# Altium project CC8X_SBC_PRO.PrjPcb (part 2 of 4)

## Sheet 06 - JTAG, SWD, MicroSD, Mini PCIe, MicroSIM.SchDoc: JTAG, SWD, MicroSD, Mini PCIe, MicroSIM
size A3; PageSetup: Record=PageOptions¦CenterHorizontal=True¦CenterVertical=True¦PrintScale=0.70¦XCorrection=1.00¦YCorrection=1.00¦PrintKind=0¦BorderSize=5000000¦LeftOffset=0¦BottomOffset=0¦Orientation=2¦PaperLength=4200¦PaperWidth=2970¦Scale=100¦PaperSource=7¦PrintQuality=600¦MediaType=1¦DitherType=10¦PaperKind=A4¦PrintScaleMode=1; Author: Juan Anzola; SheetNumber: 6; SheetTotal: 17
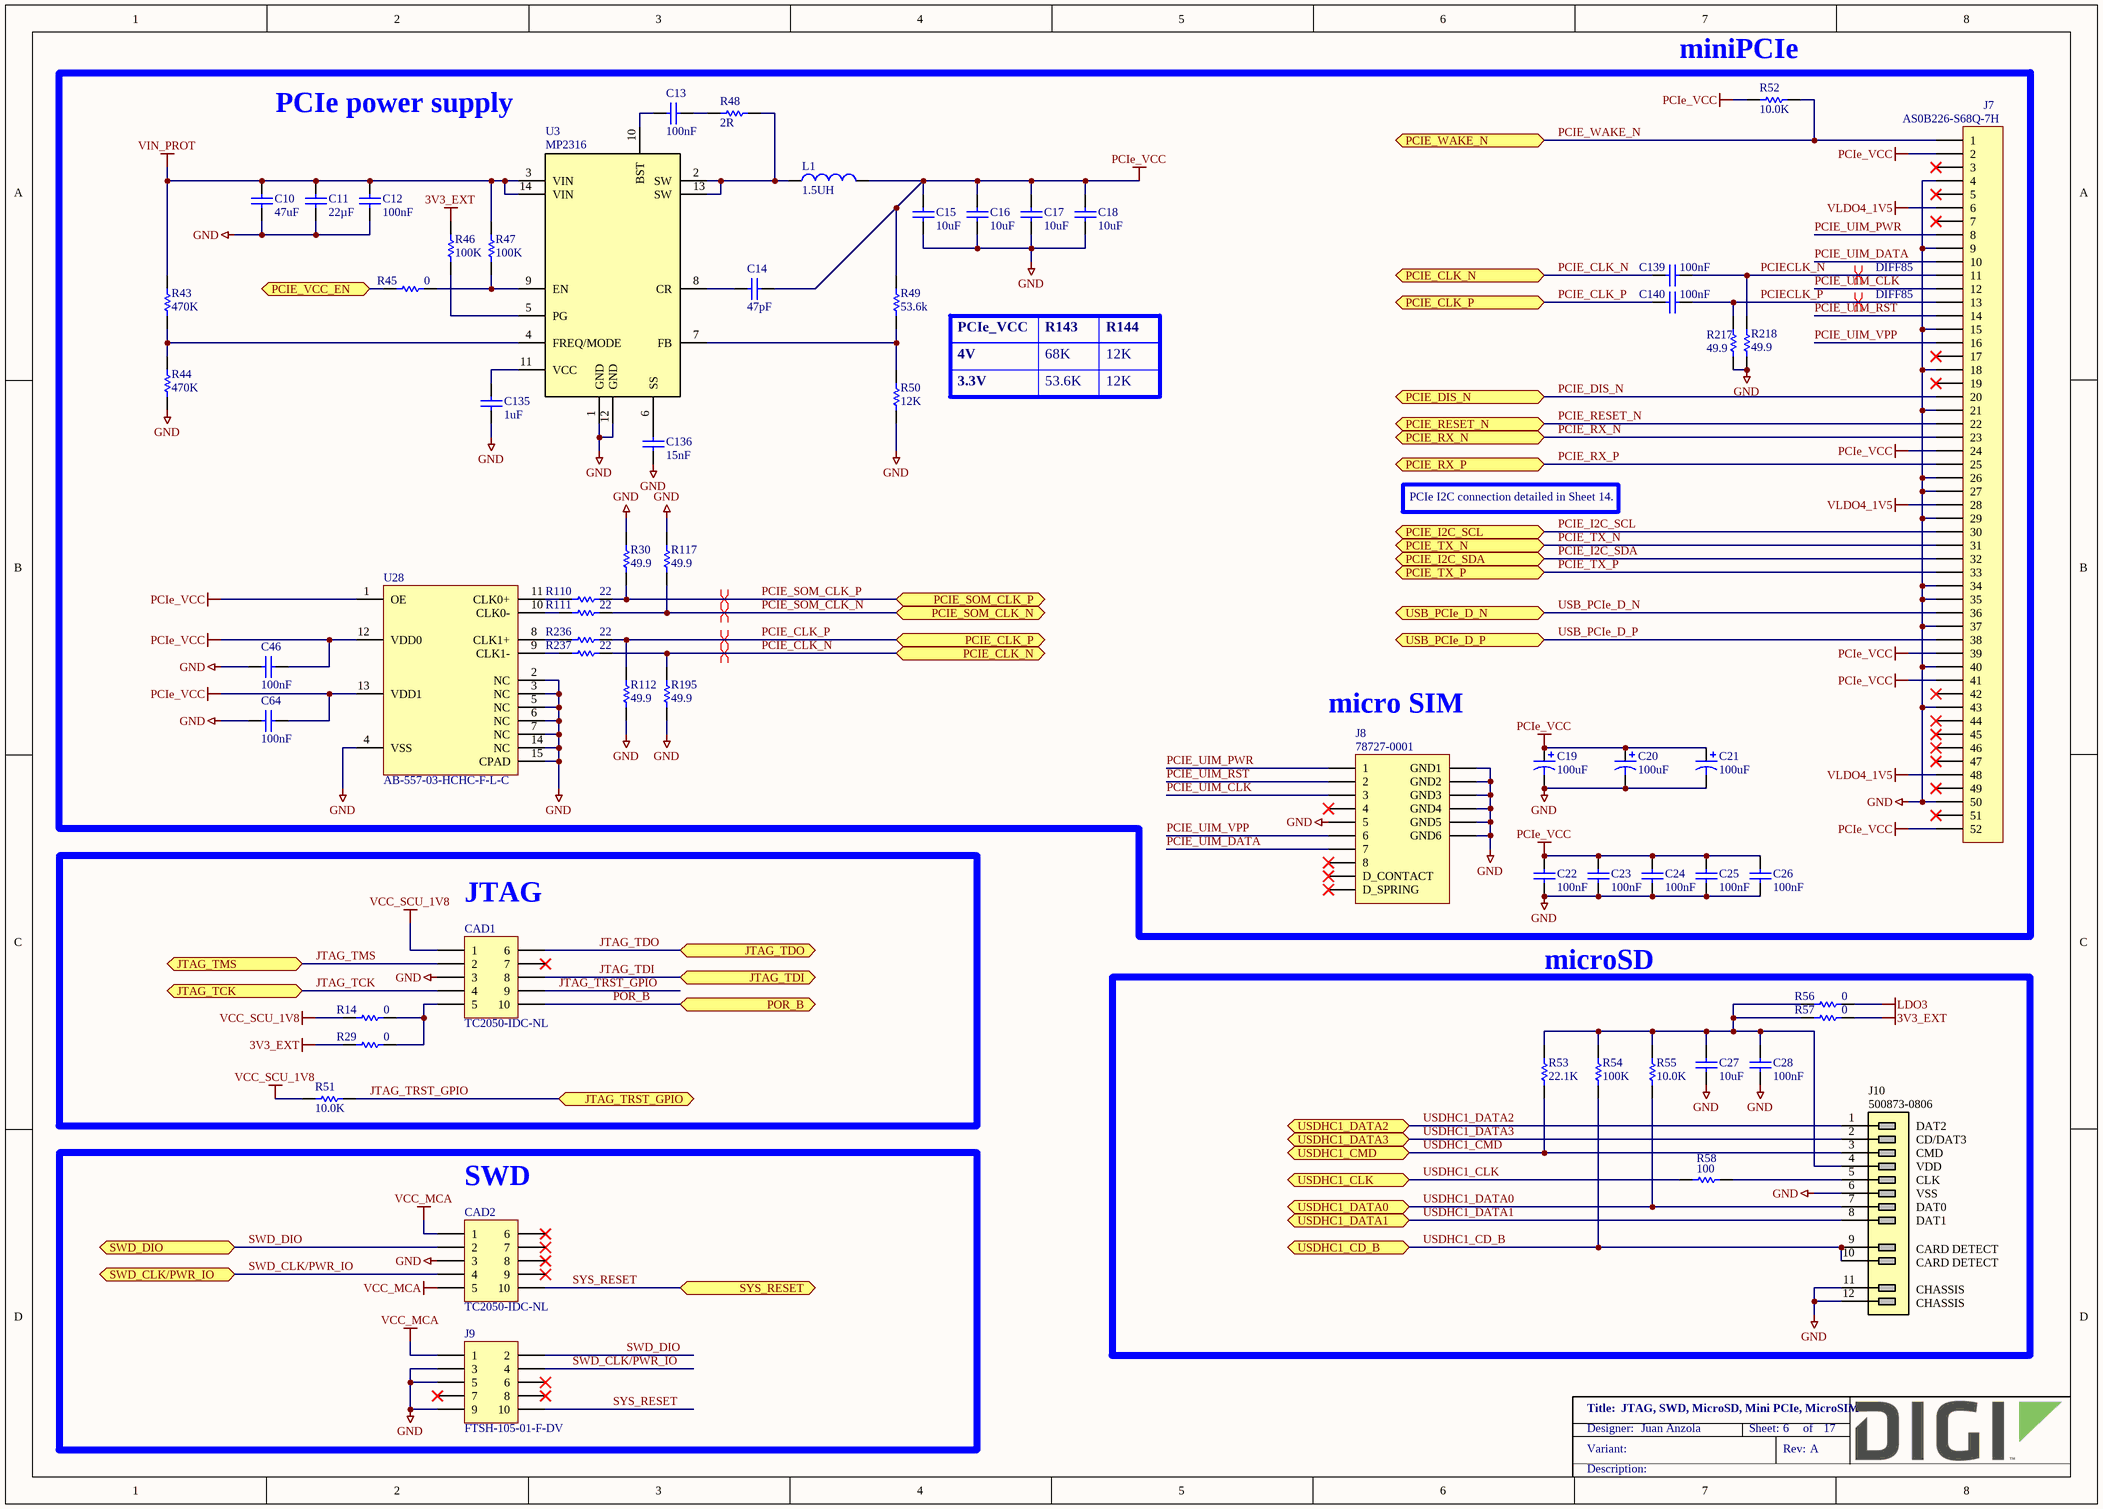
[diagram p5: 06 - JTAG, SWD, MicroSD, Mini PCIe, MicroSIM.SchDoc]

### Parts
C10  47uF  [CAPC2013X145N]
C11  22µF  [CAPC1608X90N]
C12  100nF  [CAPC1005X55N]
C13  100nF  [CAPC1005X55N]
C14  47pF  [CAPC1005X55N]
C15  10uF  [CAPC2013X135N]
C16  10uF  [CAPC2013X135N]
C17  10uF  [CAPC2013X135N]
C18  10uF  [CAPC2013X135N]
C19  100uF  [CAPMP3216X120N]
C20  100uF  [CAPMP3216X120N]
C21  100uF  [CAPMP3216X120N]
C22  100nF  [CAPC1005X55N]
C23  100nF  [CAPC1005X55N]
C24  100nF  [CAPC1005X55N]
C25  100nF  [CAPC1005X55N]
C26  100nF  [CAPC1005X55N]
C27  10uF  [CAPC1005X55N]
C28  100nF  [CAPC1005X55N]
C46  100nF  [CAPC1005X55N]
C64  100nF  [CAPC1005X55N]
C135  1uF  [CAPC1608X90N]
C136  15nF  [CAPC1005X55N]
C139  100nF  [CAPC1005X55N]
C140  100nF  [CAPC1005X55N]
CAD1  TC2050-IDC-NL  [TC_TC2050-IDC-NL]  (no BOM)
CAD2  TC2050-IDC-NL  [TC_TC2050-IDC-NL]  (no BOM)
J7  Manufacturer_Part_Number: AS0B226-S68Q-7H  [FOXCONN_AS0B221-S68Q-7H]  (hidden comment: PCIe Minicard)
J8  78727-0001  [MOLEX_78727-0001]
J9  FTSH-105-01-F-DV  [SAMTEC_FTSH-105-01-F-DV]
J10  500873-0806  [MOLEX_500873-0806]
L1  1.5UH  [INDM_SRP4020TA]
R14  0  [RESC1005X40N]
R29  0  [RESC1005X40N]
R30  49.9  [RESC1005X40N]
R43  470K  [RESC1005X40N]
R44  470K  [RESC1005X40N]
R45  0  [RESC1005X40N]
R46  100K  [RESC1005X40N]
R47  100K  [RESC1005X40N]
R48  2R  [RESC1609X55N]
R49  53.6k  [RESC1609X55N]
R50  12K  [RESC1609X55N]
R51  10.0K  [RESC1005X40N]
R52  10.0K  [RESC1005X40N]
R53  22.1K  [RESC1005X40N]
R54  100K  [RESC1005X40N]
R55  10.0K  [RESC1005X40N]
R56  0  [RESC1005X40N]
R57  0  [RESC1005X40N]
R58  100  [RESC1005X40N]
R110  22  [RESC1005X40N]
R111  22  [RESC1005X40N]
R112  49.9  [RESC1005X40N]
R117  49.9  [RESC1005X40N]
R195  49.9  [RESC1005X40N]
R217  49.9  [RESC1005X40N]
R218  49.9  [RESC1005X40N]
R236  22  [RESC1005X40N]
R237  22  [RESC1005X40N]
U3  MP2316  [QFN_MPS_MP2316]
U28  AB-557-03-HCHC-F-L-C  [QFN50P320X250X90-15T140X210N]

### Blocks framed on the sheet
JTAG: CAD1 R14 R29 R51
microSD: C27 C28 J10 R53-R58
SWD: CAD2 J9

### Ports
JTAG_TCK (bidir), JTAG_TDI (bidir), JTAG_TDO (bidir), JTAG_TMS (bidir), JTAG_TRST_GPIO (bidir), PCIE_CLK_N (bidir), PCIE_CLK_P (bidir), PCIE_DIS_N (bidir), PCIE_I2C_SCL (bidir), PCIE_I2C_SDA (bidir), PCIE_RESET_N (bidir), PCIE_RX_N (bidir), PCIE_RX_P (bidir), PCIE_SOM_CLK_N (bidir), PCIE_SOM_CLK_P (bidir), PCIE_TX_N (bidir), PCIE_TX_P (bidir), PCIE_VCC_EN (bidir), PCIE_WAKE_N (bidir), POR_B (bidir), SWD_CLK/PWR_IO (bidir), SWD_DIO (bidir), SYS_RESET (bidir), USB_PCIe_D_N (bidir), USB_PCIe_D_P (bidir), USDHC1_CD_B (bidir), USDHC1_CLK (bidir), USDHC1_CMD (bidir), USDHC1_DATA0 (bidir), USDHC1_DATA1 (bidir), USDHC1_DATA2 (bidir), USDHC1_DATA3 (bidir)

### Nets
3V3_EXT: R29.1 R46.1 R57.2
GND: C10.1 C11.1 C12.1 C15.1 C16.1 C17.1 C18.1 C19.2 C20.2 C21.2 C22.1 C23.1 C24.1 C25.1 C26.1 C27.1 C28.1 C46.2 C64.2 C135.1 C136.1 CAD1.3 CAD2.3 J7.4 J7.9 J7.15 J7.18 J7.21 J7.26 J7.27 J7.29 J7.34 J7.35 J7.37 J7.40 J7.43 J7.50 J8.5 J8.11(GND1) J8.12(GND2) J8.13(GND3) J8.14(GND4) J8.15(GND5) J8.16(GND6) J9.3 J9.5 J9.9 J10.6 J10.11 J10.12 R30.2 R44.1 R50.1 R112.1 R117.2 R195.1 R217.1 R218.1 U3.1(GND) U3.12(GND) U28.2(NC) U28.3(NC) U28.4(VSS) U28.5(NC) U28.6(NC) U28.7(NC) U28.14(NC) U28.15(CPAD)
LDO3: R56.2
PCIe_VCC: C14.2 C15.2 C16.2 C17.2 C18.2 C19.1 C20.1 C21.1 C22.2 C23.2 C24.2 C25.2 C26.2 C46.1 C64.1 J7.2 J7.24 J7.39 J7.41 J7.52 L1.2 R49.2 R52.2 U28.1(OE) U28.12(VDD0) U28.13(VDD1)
VCC_MCA: CAD2.1 CAD2.5 J9.1
VCC_SCU_1V8: CAD1.1 R14.1 R51.2
VIN_PROT: C10.2 C11.2 C12.2 R43.2 R47.2 U3.3(VIN) U3.14(VIN)
VLDO4_1V5: J7.6 J7.28 J7.48
JTAG_TCK: CAD1.4 ; port JTAG_TCK
JTAG_TDI: CAD1.8 ; port JTAG_TDI
JTAG_TDO: CAD1.6 ; port JTAG_TDO
JTAG_TMS: CAD1.2 ; port JTAG_TMS
JTAG_TRST_GPIO: CAD1.9 R51.1 ; port JTAG_TRST_GPIO
PCIE_CLK_N: C139.1 R195.2 R237.2 ; port PCIE_CLK_N
PCIE_CLK_P: C140.1 R112.2 R236.2 ; port PCIE_CLK_P
PCIE_DIS_N: J7.20 ; port PCIE_DIS_N
PCIE_I2C_SCL: J7.30 ; port PCIE_I2C_SCL
PCIE_I2C_SDA: J7.32 ; port PCIE_I2C_SDA
PCIE_RESET_N: J7.22 ; port PCIE_RESET_N
PCIE_RX_N: J7.23 ; port PCIE_RX_N
PCIE_RX_P: J7.25 ; port PCIE_RX_P
PCIE_SOM_CLK_N: R111.2 R117.1 ; port PCIE_SOM_CLK_N
PCIE_SOM_CLK_P: R30.1 R110.2 ; port PCIE_SOM_CLK_P
PCIE_TX_N: J7.31 ; port PCIE_TX_N
PCIE_TX_P: J7.33 ; port PCIE_TX_P
PCIE_UIM_CLK: J7.12 J8.3
PCIE_UIM_DATA: J7.10 J8.7
PCIE_UIM_PWR: J7.8 J8.1
PCIE_UIM_RST: J7.14 J8.2
PCIE_UIM_VPP: J7.16 J8.6
PCIE_VCC_EN: R45.1 ; port PCIE_VCC_EN
PCIE_WAKE_N: J7.1 R52.1 ; port PCIE_WAKE_N
PCIECLK_N: C139.2 J7.11 R218.2
PCIECLK_P: C140.2 J7.13 R217.2
POR_B: CAD1.10 ; port POR_B
SWD_CLK/PWR_IO: CAD2.4 J9.4 ; port SWD_CLK/PWR_IO
SWD_DIO: CAD2.2 J9.2 ; port SWD_DIO
SYS_RESET: CAD2.10 J9.10 ; port SYS_RESET
USB_PCIe_D_N: J7.36 ; port USB_PCIe_D_N
USB_PCIe_D_P: J7.38 ; port USB_PCIe_D_P
USDHC1_CD_B: J10.9 J10.10 R54.2 ; port USDHC1_CD_B
USDHC1_CLK: R58.1 ; port USDHC1_CLK
USDHC1_CMD: J10.3 R53.1 ; port USDHC1_CMD
USDHC1_DATA0: J10.7 R55.1 ; port USDHC1_DATA0
USDHC1_DATA1: J10.8 ; port USDHC1_DATA1
USDHC1_DATA2: J10.1 ; port USDHC1_DATA2
USDHC1_DATA3: J10.2 ; port USDHC1_DATA3
NetC13_1: C13.1 U3.10(BST)
NetC13_2: C13.2 R48.1
NetC14_1: C14.1 U3.8(CR)
NetC27_2: C27.2 C28.2 J10.4 R53.2 R54.1 R55.2 R56.1 R57.1
NetC135_2: C135.2 U3.11(VCC)
NetC136_2: C136.2 U3.6(SS)
NetCAD1_5: CAD1.5 R14.2 R29.2
NetJ10_5: J10.5 R58.2
NetL1_1: L1.1 R48.2 U3.2(SW) U3.13(SW)
NetR43_1: R43.1 R44.2 U3.4(FREQ/MODE)
NetR45_2: R45.2 R47.1 U3.9(EN)
NetR46_2: R46.2 U3.5(PG)
NetR49_1: R49.1 R50.2 U3.7(FB)
NetR110_1: R110.1 U28.11(CLK0+)
NetR111_1: R111.1 U28.10(CLK0-)
NetR236_1: R236.1 U28.8(CLK1+)
NetR237_1: R237.1 U28.9(CLK1-)

Not connected (* = marked no-connect by the designer): CAD1 7*; CAD2 6* 7* 8* 9*; J7 3* 5* 7* 17* 19* 42* 44* 45* 46* 47* 49* 51*; J8 4* 8* 9(D_CONTACT)* 10(D_SPRING)*; J9 6* 7* 8*

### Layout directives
differential pair; net class DIFF85: PCIECLK_N, PCIECLK_P
differential pair: PCIE_CLK_N, PCIE_CLK_P, PCIE_SOM_CLK_N, PCIE_SOM_CLK_P

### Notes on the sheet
- (near R52) miniPCIe
- (near U3) PCIe power supply
- PCIe_VCC
- 4V
- R143
- 68K
- R144
- 12K
- 3.3V
- 53.6K
- PCIe I2C connection detailed in Sheet 14.
- (near J8) micro SIM

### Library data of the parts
C10 = 1000501: CAP CER 47UF 6.3V 20% X5R 0805; Part_Type: Capacitor; Manufacturer: Taiyo Yuden; Manufacturer_Part_Number: JMK212BJ476MG-T; Digi_PN: 14050627; Component_Life_Cycle_State: Reviewed; Area: 6.4; Project: SDR Prototype RF Board
C11 = 1000998: CAP CER 22UF 10V 20% X5R 0603; Part_Type: Capacitor; Manufacturer: Samsung; Manufacturer_Part_Number: CL10A226MP8NUNE; Manufacturer_Alt_1: TDK Corporation; Manufacturer_Alt_1_Part_Number: C1608X5R1A226M080AC; Digi_PN: 14050684; Component_Life_Cycle_State: Reviewed; Area: 2.27; Project: ConnectCore i.MX6 module; Tolerance: 20
C12 C46 C64 = 1000918: CAP CER 0.1UF 50V 10% X7R 0402; Part_Type: Capacitor; Manufacturer: TDK Corporation; Manufacturer_Part_Number: C1005X7R1H104K050BB; Digi_PN: 14050715; Component_Life_Cycle_State: Reviewed; Area: 0.95; Project: DTM3.0
C13 = 1000006: CAP 100nF 16V 10% X7R 0402; Part_Type: Capacitor; Manufacturer: Murata; Manufacturer_Part_Number: GRM155R71C104KA88D; Digi_PN: 14050552; Component_Life_Cycle_State: CAD Reviewed; Area: 0.95; Project: KITT; Tolerance: 10
C14 = 1000007: CAP 47pF 50V 5% NP0 0402; Part_Type: Capacitor; Manufacturer: Murata; Manufacturer_Part_Number: GRM1555C1H470JA01D; Manufacturer_Alt_1: AVX Corporation; Manufacturer_Alt_1_Part_Number: 04025A470JAT2A; Note: 14050747 is Digi No. for GE WDNU; Digi_PN: 14050309; Component_Life_Cycle_State: CAD Reviewed; Area: 0.95; Project: KITT; Temp_Coef: C0G, NP0
C15-C18 = 1000111: CAP CER 10UF 16V 10% X5R 0805; Part_Type: Capacitor; Manufacturer: Murata; Manufacturer_Part_Number: GRM21BR61C106KE15L; Digi_PN: 14050701; Component_Life_Cycle_State: Proven; Area: 3.99; Project: Adjustable Foundation; Tolerance: 10
C19-C21 = 1001196: CAP TANT 100UF 6.3V 20% 1206; Part_Type: Capacitor; Manufacturer: Rohm; Manufacturer_Part_Number: TCTAL0J107M8R; Digi_PN: 14050490; Component_Life_Cycle_State: Reviewed; Area: 8.01; Project: CCWMX6_SBC board
C22-C26 C28 = 1000006: CAP 100nF 16V 10% X7R 0402; Part_Type: Capacitor; Manufacturer: Murata; Manufacturer_Part_Number: GRM155R71C104KA88D; Component_Life_Cycle_State: CAD Reviewed; Area: 0.95; Project: KITT; Tolerance: 10; Digi_PN: 14050552
C27 = 1001168: CAP CER 10UF 10V 20% X5R 0402; Part_Type: Capacitor; Manufacturer: Samsung; Manufacturer_Part_Number: CL05A106MP5NUNC; Digi_PN: 14050689; Component_Life_Cycle_State: Reviewed; Area: 0.95; Project: CCWMX6_SBC board
C135 = 1000110: CAP CER 1UF 25V 10% X5R 0603; Part_Type: Capacitor; Manufacturer: Murata; Manufacturer_Part_Number: GRM188R61E105KA12D; Manufacturer_Alt_1: AVX Corporation; Manufacturer_Alt_1_Part_Number: TMK107BJ105KA-T; Note: 14050758  = Digi No. for GE WDNU; Digi_PN: 14050618; Component_Life_Cycle_State: Reviewed; Area: 2.27; Project: Adjustable Foundation
C136 = 1000512: CAP CER 0.015UF 16V 10% X7R 0402; Part_Type: Capacitor; Manufacturer: Murata; Manufacturer_Part_Number: GRM155R71C153KA01D; Digi_PN: 14050713; Component_Life_Cycle_State: CAD Reviewed; Area: 0.95; Project: Cellular Proof of Concept
C139 C140 = 1000006: CAP 100nF 16V 10% X7R 0402; Part_Type: Capacitor; Manufacturer: Murata; Manufacturer_Part_Number: GRM155R71C104KA88D; Digi_PN: 14050552; Component_Life_Cycle_State: CAD Reviewed; Area: 0,95; Project: KITT; Tolerance: 10
CAD1 CAD2 = CAD0066: CBL PLUG-OF-NAILS 10-PIN; Part_Type: Test Point; Component_Life_Cycle_State: Created; Area: 8; Project: CCWMX6_SBC board
J7 = 1001130: SMCONN,MINI PCI EXP, 6.8MM HT; Part_Type: Connector; Manufacturer: Foxconn; Digi_PN: 18000349; Component_Life_Cycle_State: Reviewed; Area: 150; Project: CCWMX6_SBC board
J8 = 1001120: MEMORY CARD 6POS PUSH/PULL SMD; Part_Type: Connector; Manufacturer: Molex; Digi_PN: 18000638; Component_Life_Cycle_State: Reviewed; Area: 217; Project: CCWMX6_SBC board
J9 = 1000034: CONN HEADER 10POS DUAL .05" SMD; Part_Type: Connector; Manufacturer: Samtec; Note: 18000715 = Digi No. for GE WDNU; Digi_PN: 18000539; Component_Life_Cycle_State: Proven; Area: 43,55; Project: Adjustable Foundation
J10 = 1001118: CONN TRANSFLSH R/A PUSH-PUSH SMD; Part_Type: Connector; Manufacturer: Molex; Digi_PN: MB03015; Component_Life_Cycle_State: Reviewed; Area: 213; Project: CCWMX6_SBC board
L1 = 1001912: FIXED IND 1.5UH 4.5A 42 MOHM SMD; Manufacturer: Bourns; Manufacturer_Part_Number: SRP4020TA-1R5M; Digi_PN: 21000530; Component_Life_Cycle_State: Reviewed; Area: 24.75; Project: CCWMX6_SBC board; Tolerance: ±20%
R14 R29 R45 R56 R57 = 1000076: RES 0.0 OHM 1/10W 0402 SMD; Part_Type: Resistor; Manufacturer: Panasonic - ECG; Manufacturer_Part_Number: ERJ-2GE0R00X; Component_Life_Cycle_State: Proven; Area: 0.95; Project: Adjustable Foundation; Power_WV_SRF: 10; Digi_PN: 13050387
R30 R112 R117 R195 = 1000466: RES 49.9 OHM 1/10W 1% 0402 SMD; Part_Type: Resistor; Manufacturer: Panasonic - ECG; Manufacturer_Part_Number: ERJ-2RKF49R9X; Digi_PN: 13051083; Component_Life_Cycle_State: CAD Reviewed; Area: 0.95; Project: KITT; Power_WV_SRF: 100
R43 R44 = 1000701: RES 470K OHM 1/10W 1% 0402 SMD; Part_Type: Resistor; Manufacturer: Panasonic - ECG; Manufacturer_Part_Number: ERJ-2RKF4703X; Digi_PN: 13051092; Component_Life_Cycle_State: CAD Reviewed; Area: 0.95; Project: KITT; Power_WV_SRF: 100
R46 R47 R54 = 1000480: RES 100K OHM 1/10W 1% 0402 SMD; Part_Type: Resistor; Manufacturer: Panasonic - ECG; Manufacturer_Part_Number: ERJ-2RKF1003X; Digi_PN: 13051063; Component_Life_Cycle_State: CAD Reviewed; Area: 0.95; Project: KITT; Power_WV_SRF: 100
R48 = 1001916: RES SMD 2 OHM 5% 1/10W 0603; Part_Type: Resistor; Manufacturer: Panasonic - ECG; Manufacturer_Part_Number: ERJ-3GEYJ2R0V; Digi_PN: 13050488; Component_Life_Cycle_State: Reviewed; Area: 4.5; Project: CCWMX6_SBC board; Power_WV_SRF: 100; Tolerance: 1
R49 = 1001518: RES 53.6K OHM 1/10W 1% 0603 SMD; Part_Type: Resistor; Manufacturer: Panasonic - ECG; Manufacturer_Part_Number: ERJ-3EKF5362V; Digi_PN: 13051064; Component_Life_Cycle_State: Reviewed; Area: 2.5; Project: WDNU-II
R50 = 1001200: RES 12.0K OHM 1/10W 1% 0603 SMD; Part_Type: Resistor; Manufacturer: Yageo; Manufacturer_Part_Number: RC0603FR-0712KL; Digi_PN: 13050531; Component_Life_Cycle_State: Reviewed; Area: 2.5; Project: LuCoV2; Power_WV_SRF: 100; Tolerance: 1
R51 R52 R55 = 1000537: RES 10.0K OHM 1/10W 1% 0402 SMD; Part_Type: Resistor; Manufacturer: Panasonic - ECG; Manufacturer_Part_Number: ERJ-2RKF1002X; Component_Life_Cycle_State: CAD Reviewed; Area: 0.95; Project: KITT; Power_WV_SRF: 100; Digi_PN: 13051084
R53 = 1001149: RES 22.1K OHM 1/16W 1% 0402 SMD; Part_Type: Resistor; Manufacturer: Vishay Dale; Manufacturer_Part_Number: CRCW040222K1FKED; Digi_PN: 13050450; Component_Life_Cycle_State: Reviewed; Area: 0.95; Project: CCWMX6_SBC board; Power_WV_SRF: 0.063; Tolerance: ±100ppm/°C
R58 = 1000467: RES 100 OHM 1/10W 1% 0402 SMD; Part_Type: Resistor; Manufacturer: Panasonic - ECG; Manufacturer_Part_Number: ERJ-2RKF1000X; Component_Life_Cycle_State: CAD Reviewed; Area: 0.95; Project: KITT; Digi_PN: 13051087
R110 R111 R236 R237 = 1000601: RES 22.0 OHM 1/10W 1% 0402 SMD; Part_Type: Resistor; Manufacturer: Panasonic - ECG; Manufacturer_Part_Number: ERJ-2RKF22R0X; Digi_PN: 13051089; Component_Life_Cycle_State: CAD Reviewed; Area: 0.95; Project: KITT; Power_WV_SRF: 100
R217 R218 = 1000466: RES 49.9 OHM 1/10W 1% 0402 SMD; Part_Type: Resistor; Manufacturer: Panasonic - ECG; Manufacturer_Part_Number: ERJ-2RKF49R9X; Digi_PN: 13051083; Component_Life_Cycle_State: CAD Reviewed; Area: 0,95; Project: KITT; Power_WV_SRF: 100
U3 = 1001907: IC REG BUCK ADJ 3A SYNC; Manufacturer: Linear Technology; Manufacturer_Part_Number: MP2316GD; Digi_PN: 17050862; Component_Life_Cycle_State: Reviewed; Area: 9.375; Project: CCWMX6_SBC board
U28 = 1002449: SMIC PCIE CLOCK GEN 100MHZ 14QFN; Part_Type: IC; Manufacturer: Abracon Corporation; Digi_PN: 16000101; Component_Life_Cycle_State: Created; Area: 16; Project: DIGI CC8X SOM

## Sheet 07 - Console, UART, CAN.SchDoc: Console, UART, CAN
size A3; PageSetup: Record=PageOptions¦CenterHorizontal=True¦CenterVertical=True¦PrintScale=0.70¦XCorrection=1.00¦YCorrection=1.00¦PrintKind=0¦BorderSize=5000000¦LeftOffset=0¦BottomOffset=0¦Orientation=2¦PaperLength=4200¦PaperWidth=2970¦Scale=100¦PaperSource=7¦PrintQuality=600¦MediaType=1¦DitherType=10¦PaperKind=A4¦PrintScaleMode=1; Author: Juan Anzola; SheetNumber: 7; SheetTotal: 17
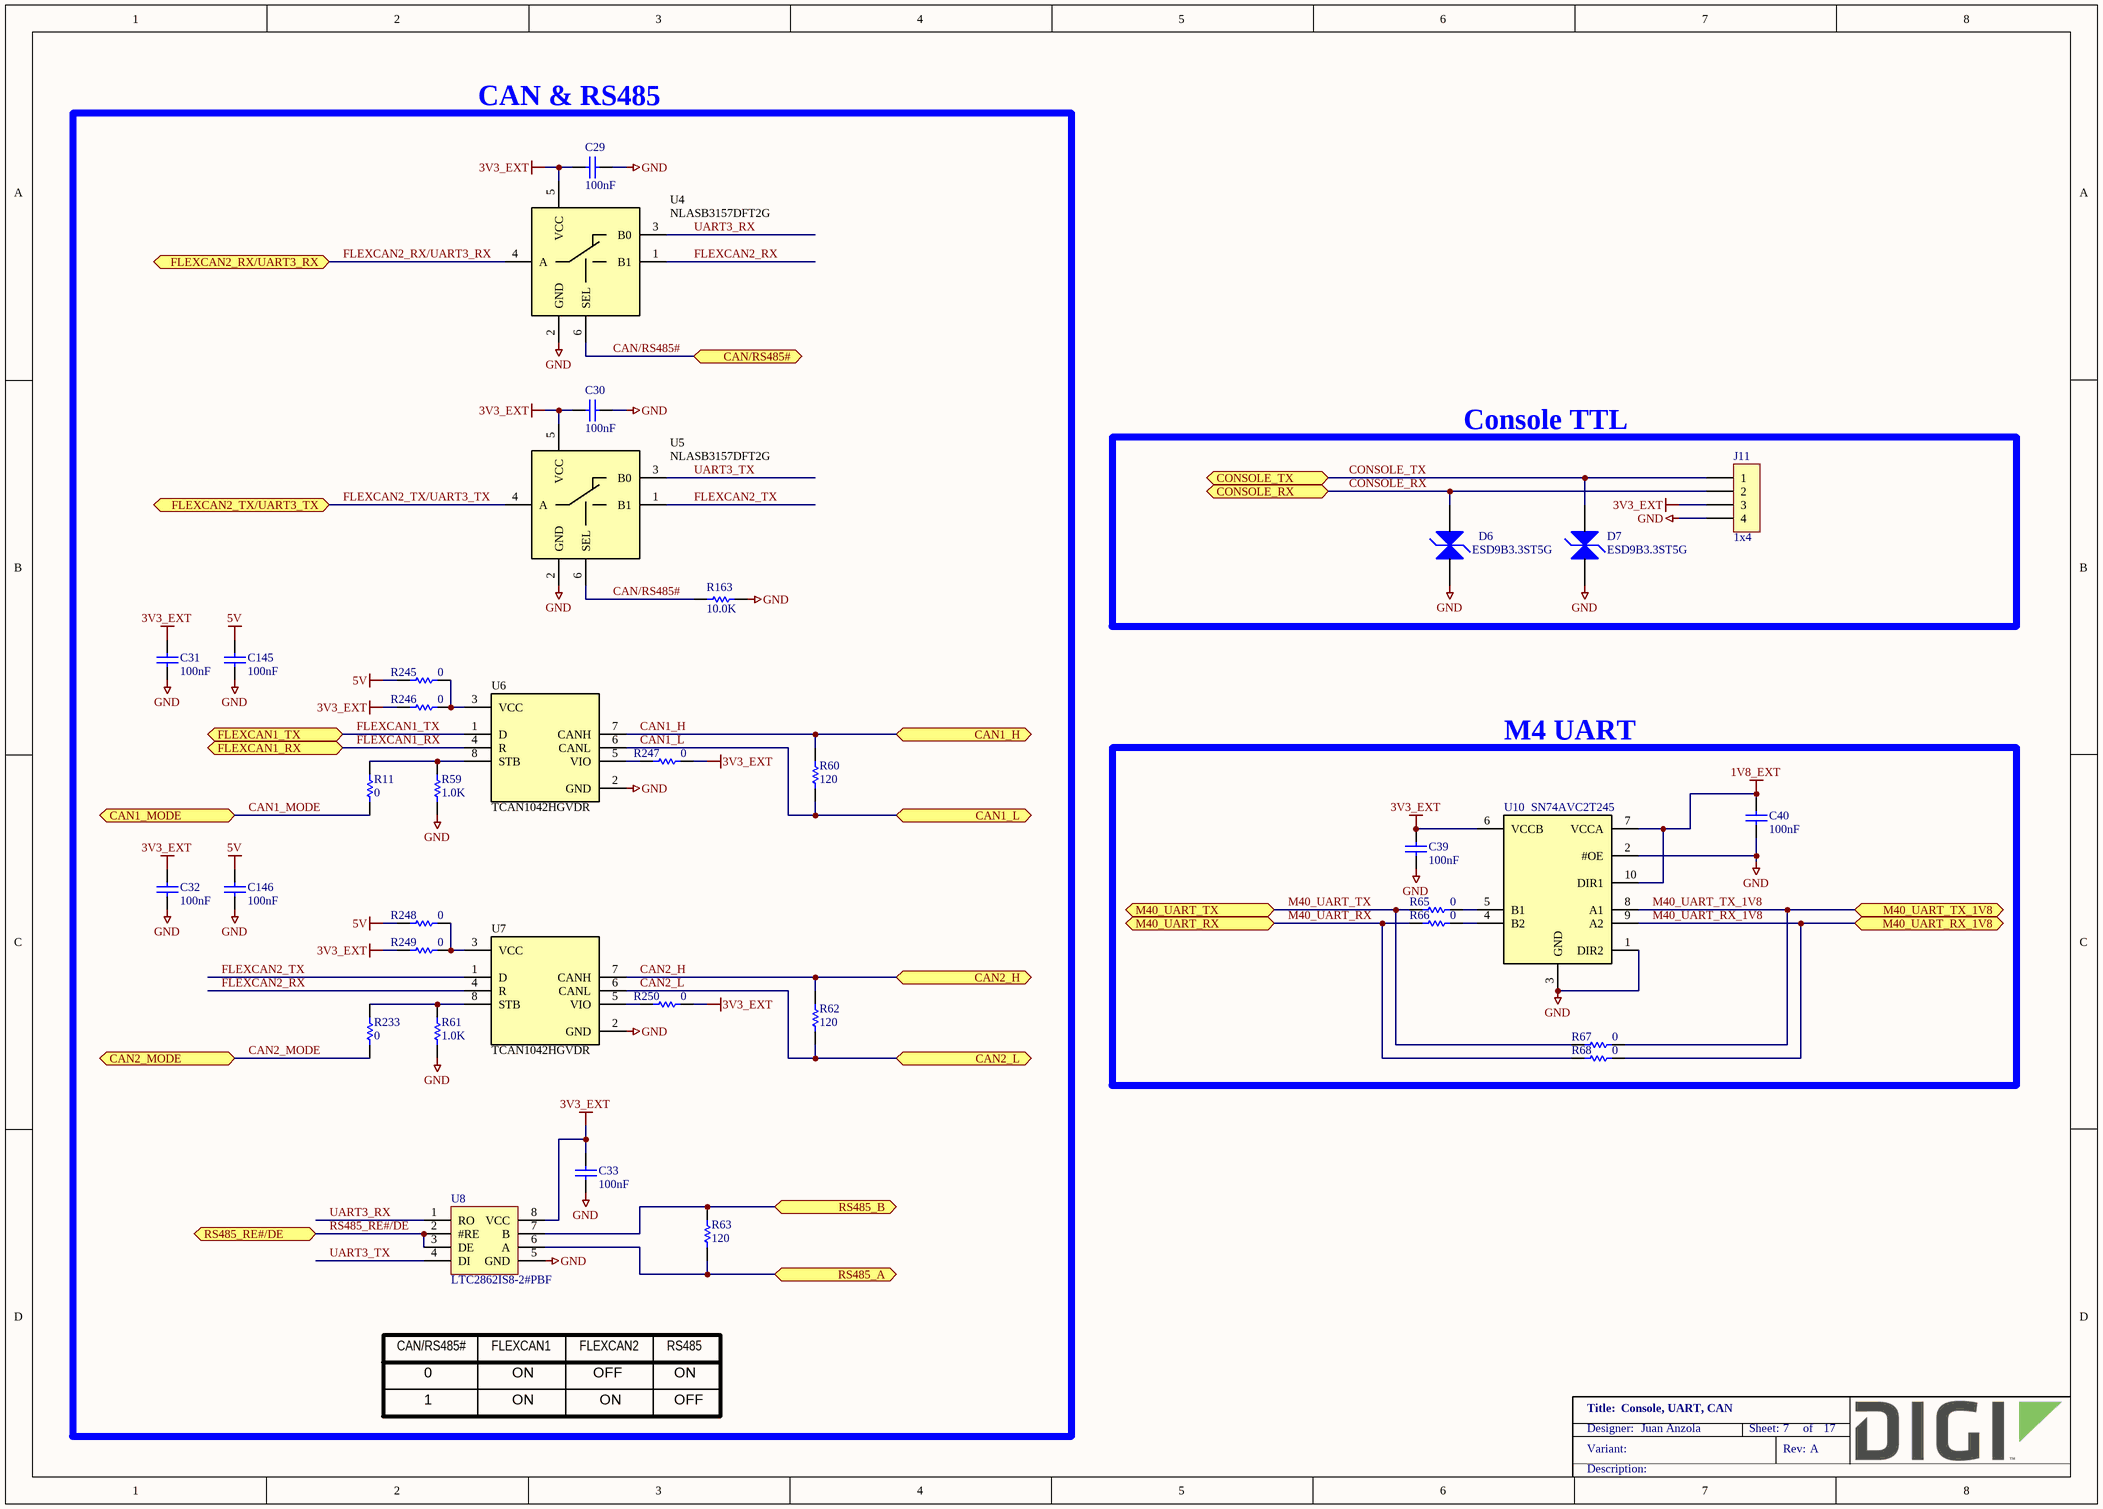
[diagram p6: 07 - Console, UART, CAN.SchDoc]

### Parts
C29  100nF  [CAPC1005X55N]
C30  100nF  [CAPC1005X55N]
C31  100nF  [CAPC1005X55N]
C32  100nF  [CAPC1005X55N]
C33  100nF  [CAPC1005X55N]
C39  100nF  [CAPC1005X55N]
C40  100nF  [CAPC1005X55N]
C145  100nF  [CAPC1005X55N]
C146  100nF  [CAPC1005X55N]
D6  ESD9B3.3ST5G  [SODFL1006X43AN12]
D7  ESD9B3.3ST5G  [SODFL1006X43AN12]
J11  1x4  [MOLEX_53047-0410]
R11  0  [RESC1005X40N]
R59  1.0K  [RESC1005X40N]
R60  120  [RESC1005X40N]
R61  1.0K  [RESC1005X40N]
R62  120  [RESC1005X40N]
R63  120  [RESC1005X40N]
R65  0  [RESC1005X40N]
R66  0  [RESC1005X40N]
R67  0  [RESC1005X40N]
R68  0  [RESC1005X40N]
R163  10.0K  [RESC1005X40N]
R233  0  [RESC1005X40N]
R245  0  [RESC1005X40N]
R246  0  [RESC1005X40N]
R247  0  [RESC1005X40N]
R248  0  [RESC1005X40N]
R249  0  [RESC1005X40N]
R250  0  [RESC1005X40N]
U4  NLASB3157DFT2G  [SOT65P210X110-6N]
U5  NLASB3157DFT2G  [SOT65P210X110-6N]
U6  TCAN1042HGVDR  [SOIC127P600X175-8N]
U7  TCAN1042HGVDR  [SOIC127P600X175-8N]
U8  LTC2862IS8-2#PBF  [SOIC127P600X175-8N]
U10  SN74AVC2T245  [QFN40P180X140X55-10N]

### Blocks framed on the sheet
CAN & RS485: C29-C33 C145 C146 R11 R59-R63 R163 R233 R245-R250 U4-U8
Console TTL: D6 D7 J11
M4 UART: C39 C40 R65-R68 U10

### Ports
CAN1_H (bidir), CAN1_L (bidir), CAN1_MODE (bidir), CAN2_H (bidir), CAN2_L (bidir), CAN2_MODE (bidir), CAN/RS485# (bidir), CONSOLE_RX (bidir), CONSOLE_TX (bidir), FLEXCAN1_RX (bidir), FLEXCAN1_TX (bidir), FLEXCAN2_RX/UART3_RX (bidir), FLEXCAN2_TX/UART3_TX (bidir), M40_UART_RX (bidir), M40_UART_RX_1V8 (bidir), M40_UART_TX (bidir), M40_UART_TX_1V8 (bidir), RS485_A (bidir), RS485_B (bidir), RS485_RE#/DE (bidir)

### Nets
1V8_EXT: C40.2 U10.7(VCCA) U10.10(DIR1)
3V3_EXT: C29.1 C30.1 C31.2 C32.2 C33.2 C39.2 J11.3 R246.1 R247.2 R249.1 R250.2 U4.5(VCC) U5.5(VCC) U8.8(VCC) U10.6(VCCB)
5V: C145.2 C146.2 R245.1 R248.1
GND: C29.2 C30.2 C31.1 C32.1 C33.1 C39.1 C40.1 C145.1 C146.1 D6.1 D7.1 J11.4 R59.1 R61.1 R163.2 U4.2(GND) U5.2(GND) U6.2(GND) U7.2(GND) U8.5(GND) U10.1(DIR2) U10.2(#OE) U10.3(GND)
CAN1_H: R60.2 U6.7(CANH) ; port CAN1_H
CAN1_L: R60.1 U6.6(CANL) ; port CAN1_L
CAN1_MODE: R11.1 ; port CAN1_MODE
CAN2_H: R62.2 U7.7(CANH) ; port CAN2_H
CAN2_L: R62.1 U7.6(CANL) ; port CAN2_L
CAN2_MODE: R233.1 ; port CAN2_MODE
CAN/RS485#: R163.1 U4.6(SEL) U5.6(SEL) ; port CAN/RS485#
CONSOLE_RX: D6.2 J11.2 ; port CONSOLE_RX
CONSOLE_TX: D7.2 J11.1 ; port CONSOLE_TX
FLEXCAN1_RX: U6.4(R) ; port FLEXCAN1_RX
FLEXCAN1_TX: U6.1(D) ; port FLEXCAN1_TX
FLEXCAN2_RX: U4.1(B1) U7.4(R)
FLEXCAN2_RX/UART3_RX: U4.4(A) ; port FLEXCAN2_RX/UART3_RX
FLEXCAN2_TX: U5.1(B1) U7.1(D)
FLEXCAN2_TX/UART3_TX: U5.4(A) ; port FLEXCAN2_TX/UART3_TX
M40_UART_RX: R66.1 R68.1 ; port M40_UART_RX
M40_UART_RX_1V8: R68.2 U10.9(A2) ; port M40_UART_RX_1V8
M40_UART_TX: R65.1 R67.1 ; port M40_UART_TX
M40_UART_TX_1V8: R67.2 U10.8(A1) ; port M40_UART_TX_1V8
RS485_A: R63.1 U8.6(A) ; port RS485_A
RS485_B: R63.2 U8.7(B) ; port RS485_B
RS485_RE#/DE: U8.2(#RE) U8.3(DE) ; port RS485_RE#/DE
UART3_RX: U4.3(B0) U8.1(RO)
UART3_TX: U5.3(B0) U8.4(DI)
NetR11_2: R11.2 R59.2 U6.8(STB)
NetR61_2: R61.2 R233.2 U7.8(STB)
NetR65_2: R65.2 U10.5(B1)
NetR66_2: R66.2 U10.4(B2)
NetR245_2: R245.2 R246.2 U6.3(VCC)
NetR247_1: R247.1 U6.5(VIO)
NetR248_2: R248.2 R249.2 U7.3(VCC)
NetR250_1: R250.1 U7.5(VIO)

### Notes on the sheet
- CAN/RS485#
- 0
- FLEXCAN1
- ON
- FLEXCAN2
- OFF
- RS485
- 1

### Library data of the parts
C29 C30 C39 C40 = 1000006: as C139 on sheet 06 - JTAG, SWD, MicroSD, Mini PCIe, MicroSIM
C31-C33 C145 C146 = 1000006: as C22-C26 on sheet 06 - JTAG, SWD, MicroSD, Mini PCIe, MicroSIM
D6 D7 = 1001637: TVS DIODE 3.3VWM SOD923; Part_Type: Diodes; Manufacturer: On Semiconductor; Digi_PN: 17050883; Component_Life_Cycle_State: Reviewed; Area: 1,01; Project: CareTaker IV
J11 = 1001137: CONN HEADER 4POS 1.25MM VERT TIN; Part_Type: Connector; Manufacturer: Molex; Manufacturer_Part_Number: 53047-0410; Digi_PN: 18050344; Component_Life_Cycle_State: Reviewed; Area: 21.6; Project: CCWMX6_SBC board
R11 R65-R68 R233 = 1000076: RES 0.0 OHM 1/10W 0402 SMD; Part_Type: Resistor; Manufacturer: Panasonic - ECG; Manufacturer_Part_Number: ERJ-2GE0R00X; Digi_PN: 13050387; Component_Life_Cycle_State: Proven; Area: 0,95; Project: Adjustable Foundation; Power_WV_SRF: 10
R59 R61 = 1000079: RES 1.00K OHM 1/10W 1% 0402 SMD; Part_Type: Resistor; Manufacturer: Panasonic - ECG; Manufacturer_Part_Number: ERJ-2RKF1001X; Digi_PN: 13051085; Component_Life_Cycle_State: Proven; Area: 0,95; Project: Adjustable Foundation; Power_WV_SRF: 10
R60 R62 R63 = 1001158: RES 120 OHM 1/16W 1% 0402 SMD; Part_Type: Resistor; Manufacturer: Yageo; Manufacturer_Part_Number: RC0402FR-07120RL; Digi_PN: 13050832; Component_Life_Cycle_State: Reviewed; Area: 0.95; Project: CCWMX6_SBC board; Note: 13051102 = Digi No. for GE WDNU
R163 = 1000537: as R51 on sheet 06 - JTAG, SWD, MicroSD, Mini PCIe, MicroSIM
R245-R250 = 1000076: as R14 on sheet 06 - JTAG, SWD, MicroSD, Mini PCIe, MicroSIM
U4 U5 = 1001179: IC SWITCH SPDT SC88; Manufacturer: On Semiconductor; Digi_PN: 16051954; Component_Life_Cycle_State: Reviewed; Area: 4,8; Project: CCWMX6_SBC board
U6 U7 = 1002681: IC CAN TRANSEIVER HS 8SOIC; Manufacturer: Texas Instruments; Digi_PN: 16000166; Component_Life_Cycle_State: Pending; Area: 20; Project: DIGI CC8X SOM
U8 = 1001420: IC TRANSCEIVER RS485 8-SOIC; Manufacturer: Linear Technology; Digi_PN: 16052092; Component_Life_Cycle_State: Reviewed; Area: 34.75; Project: E-Gear Gateway v0.1
U10 = 1002531: IC BUS TRANSCVR TRI-ST DL 10UQFN; Manufacturer: Texas Instruments; Manufacturer_Part_Number: SN74AVC2T245RSWR; Digi_PN: 16052024; Component_Life_Cycle_State: Created; Area: 8.01; Project: DIGI CC8X SOM

## Sheet 08 - Ethernet1.SchDoc: Ethernet1
size A3; PageSetup: Record=PageOptions¦CenterHorizontal=True¦CenterVertical=True¦PrintScale=0.70¦XCorrection=1.00¦YCorrection=1.00¦PrintKind=0¦BorderSize=5000000¦LeftOffset=0¦BottomOffset=0¦Orientation=2¦PaperLength=4200¦PaperWidth=2970¦Scale=100¦PaperSource=7¦PrintQuality=600¦MediaType=1¦DitherType=10¦PaperKind=A4¦PrintScaleMode=1; Author: Juan Anzola; SheetNumber: 8; SheetTotal: 17
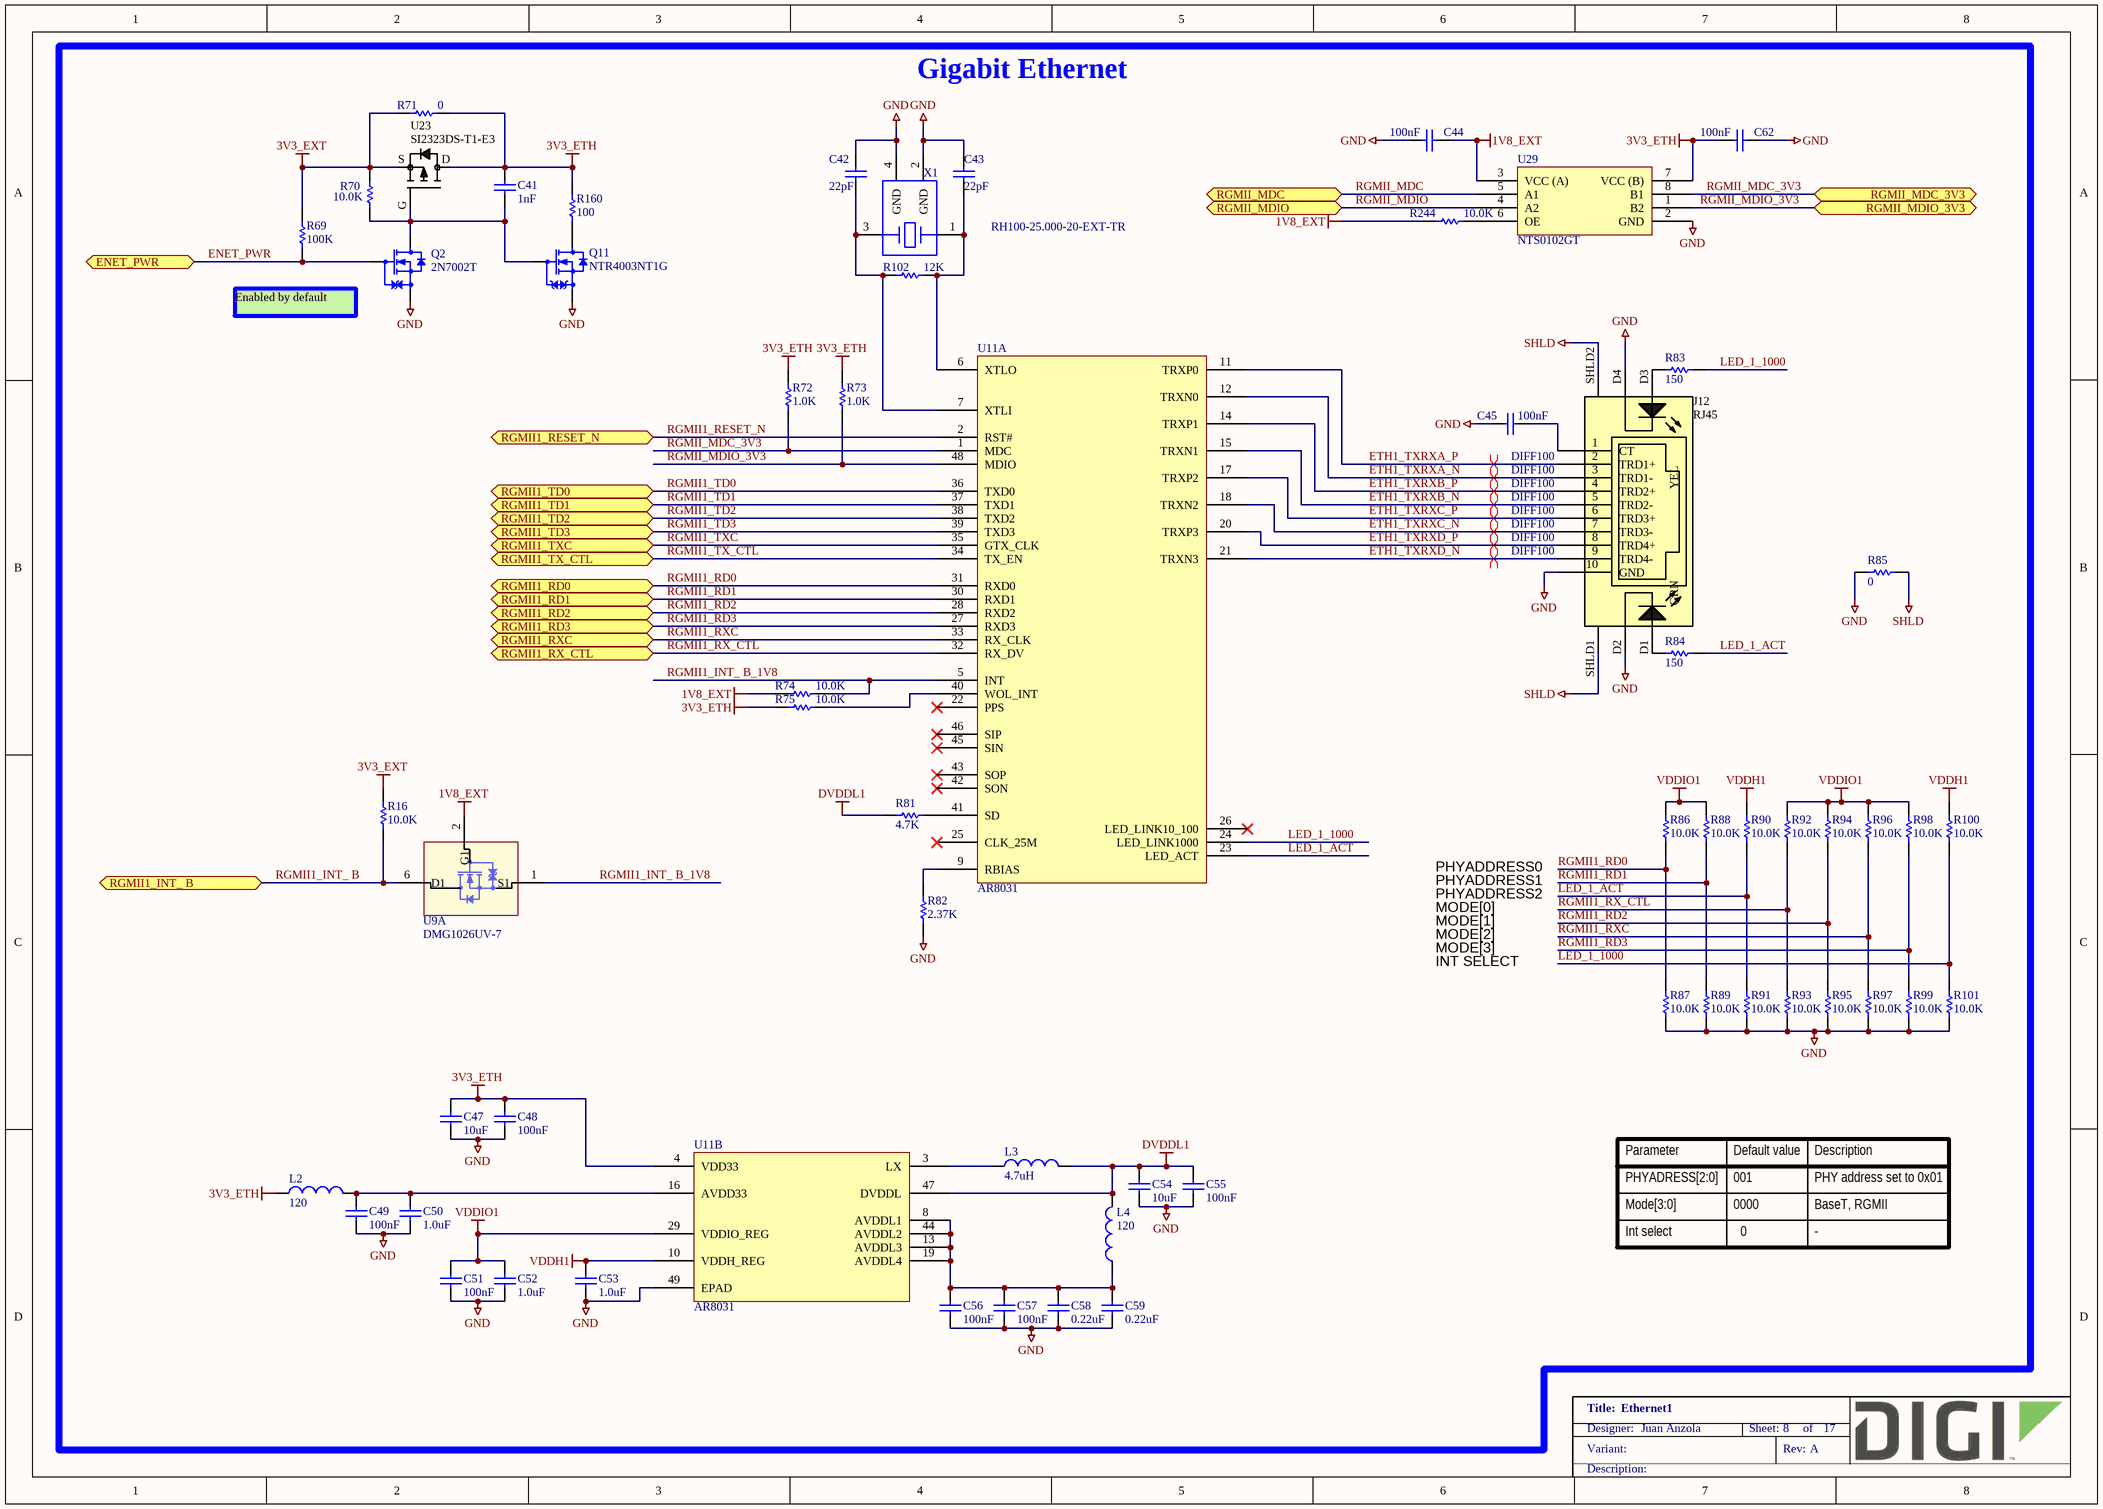
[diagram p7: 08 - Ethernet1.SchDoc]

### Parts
C41  1nF  [CAPC1005X55N]
C42  22pF  [CAPC1005X55N]
C43  22pF  [CAPC1005X55N]
C44  100nF  [CAPC1005X55N]
C45  100nF  [CAPC1005X55N]
C47  10uF  [CAPC1005X55N]
C48  100nF  [CAPC1005X55N]
C49  100nF  [CAPC1005X55N]
C50  1.0uF  [CAPC1005X55N]
C51  100nF  [CAPC1005X55N]
C52  1.0uF  [CAPC1005X55N]
C53  1.0uF  [CAPC1005X55N]
C54  10uF  [CAPC1005X55N]
C55  100nF  [CAPC1005X55N]
C56  100nF  [CAPC1005X55N]
C57  100nF  [CAPC1005X55N]
C58  0.22uF  [CAPC1005X55N]
C59  0.22uF  [CAPC1005X55N]
C62  100nF  [CAPC1005X55N]
J12  RJ45  [XMULTIPLE_XMG-J1B211]
L2  120  [INDC1005X60N]
L3  4.7uH  [INDC2520X100L60N]
L4  120  [INDC1005X60N]
Q2  2N7002T  [SOTFL50P160X80_GSD-3N]
Q11  NTR4003NT1G  [SOT95P240X110_GSD-3N]
R16  10.0K  [RESC1005X40N]
R69  100K  [RESC1005X40N]
R70  10.0K  [RESC1005X40N]
R71  0  [RESC1609X55N]
R72  1.0K  [RESC1005X40N]
R73  1.0K  [RESC1005X40N]
R74  10.0K  [RESC1005X40N]
R75  10.0K  [RESC1005X40N]
R81  4.7K  [RESC1005X40N]
R82  2.37K  [RESC1005X40N]
R83  150  [RESC1005X40N]
R84  150  [RESC1005X40N]
R85  0  [RESC3225X60N]
R86  10.0K  [RESC1005X40N]
R87  10.0K  [RESC1005X40N]
R88  10.0K  [RESC1005X40N]
R89  10.0K  [RESC1005X40N]
R90  10.0K  [RESC1005X40N]
R91  10.0K  [RESC1005X40N]
R92  10.0K  [RESC1005X40N]
R93  10.0K  [RESC1005X40N]
R94  10.0K  [RESC1005X40N]
R95  10.0K  [RESC1005X40N]
R96  10.0K  [RESC1005X40N]
R97  10.0K  [RESC1005X40N]
R98  10.0K  [RESC1005X40N]
R99  10.0K  [RESC1005X40N]
R100  10.0K  [RESC1005X40N]
R101  10.0K  [RESC1005X40N]
R102  12K  [RESC1609X55N]
R160  100  [RESC1005X40N]
R244  10.0K  [RESC1005X40N]
U9  DMG1026UV-7  [SOTFL50P160X60-6N]  (part A of 2)
U11  AR8031  [QFN40P600X600X80-49T380N]  (parts A,B of 2)
U23  SI2323DS-T1-E3  [SOT95P240X110_GSD-3N]
U29  NTS0102GT  [PSON50P195X100X50-8N]
X1  RH100-25.000-20-EXT-TR  [OSC210P320X250X90-4N]

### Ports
ENET_PWR (bidir), RGMII1_INT_ B (bidir), RGMII1_RD0 (bidir), RGMII1_RD1 (bidir), RGMII1_RD2 (bidir), RGMII1_RD3 (bidir), RGMII1_RESET_N (bidir), RGMII1_RX_CTL (bidir), RGMII1_RXC (bidir), RGMII1_TD0 (bidir), RGMII1_TD1 (bidir), RGMII1_TD2 (bidir), RGMII1_TD3 (bidir), RGMII1_TX_CTL (bidir), RGMII1_TXC (bidir), RGMII_MDC (bidir), RGMII_MDC_3V3 (bidir), RGMII_MDIO (bidir), RGMII_MDIO_3V3 (bidir)

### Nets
1V8_EXT: C44.2 R74.2 R244.1 U9.2(G1) U29.3(VCC_(A))
3V3_ETH: C41.2 C47.2 C48.2 C62.2 L2.1 R71.2 R72.2 R73.2 R75.2 R160.2 U11.4(VDD33) U23.D U29.7(VCC_(B))
3V3_EXT: R16.1 R69.1 R70.1 R71.1 U23.S
DVDDL1: C54.2 C55.2 L3.2 L4.2 R81.1 U11.47(DVDDL)
GND: C42.1 C43.1 C44.1 C45.1 C47.1 C48.1 C49.1 C50.1 C51.1 C52.1 C53.1 C54.1 C55.1 C56.1 C57.1 C58.1 C59.1 C62.1 J12.10(GND) J12.D2 J12.D4 Q2.S Q11.S R82.1 R85.1 R87.1 R89.1 R91.1 R93.1 R95.1 R97.1 R99.1 R101.1 U11.49(EPAD) U29.2(GND) X1.2(GND) X1.4(GND)
SHLD: J12.SHLD1(SHLD) J12.SHLD2(SHLD) R85.2
VDDH1: C53.2 R90.2 R100.2 U11.10(VDDH_REG)
VDDIO1: C51.2 C52.2 R86.2 R88.2 R92.2 R94.2 R96.2 R98.2 U11.29(VDDIO_REG)
ENET_PWR: Q2.G R69.2 ; port ENET_PWR
ETH1_TXRXA_N: J12.3(TRD1-) U11.12(TRXN0)
ETH1_TXRXA_P: J12.2(TRD1+) U11.11(TRXP0)
ETH1_TXRXB_N: J12.5(TRD2-) U11.15(TRXN1)
ETH1_TXRXB_P: J12.4(TRD2+) U11.14(TRXP1)
ETH1_TXRXC_N: J12.7(TRD3-) U11.18(TRXN2)
ETH1_TXRXC_P: J12.6(TRD3+) U11.17(TRXP2)
ETH1_TXRXD_N: J12.9(TRD4-) U11.21(TRXN3)
ETH1_TXRXD_P: J12.8(TRD4+) U11.20(TRXP3)
LED_1_1000: R83.2 R100.1 R101.2 U11.24(LED_LINK1000)
LED_1_ACT: R84.2 R90.1 R91.2 U11.23(LED_ACT)
RGMII1_INT_ B: R16.2 U9.6(D1) ; port RGMII1_INT_ B
RGMII1_INT_ B_1V8: R74.1 U9.1(S1) U11.5(INT)
RGMII1_RD0: R86.1 R87.2 U11.31(RXD0) ; port RGMII1_RD0
RGMII1_RD1: R88.1 R89.2 U11.30(RXD1) ; port RGMII1_RD1
RGMII1_RD2: R94.1 R95.2 U11.28(RXD2) ; port RGMII1_RD2
RGMII1_RD3: R98.1 R99.2 U11.27(RXD3) ; port RGMII1_RD3
RGMII1_RESET_N: U11.2(RST#) ; port RGMII1_RESET_N
RGMII1_RX_CTL: R92.1 R93.2 U11.32(RX_DV) ; port RGMII1_RX_CTL
RGMII1_RXC: R96.1 R97.2 U11.33(RX_CLK) ; port RGMII1_RXC
RGMII1_TD0: U11.36(TXD0) ; port RGMII1_TD0
RGMII1_TD1: U11.37(TXD1) ; port RGMII1_TD1
RGMII1_TD2: U11.38(TXD2) ; port RGMII1_TD2
RGMII1_TD3: U11.39(TXD3) ; port RGMII1_TD3
RGMII1_TX_CTL: U11.34(TX_EN) ; port RGMII1_TX_CTL
RGMII1_TXC: U11.35(GTX_CLK) ; port RGMII1_TXC
RGMII_MDC: U29.5(A1) ; port RGMII_MDC
RGMII_MDC_3V3: R72.1 U11.1(MDC) U29.8(B1) ; port RGMII_MDC_3V3
RGMII_MDIO: U29.4(A2) ; port RGMII_MDIO
RGMII_MDIO_3V3: R73.1 U11.48(MDIO) U29.1(B2) ; port RGMII_MDIO_3V3
NetC41_1: C41.1 Q2.D Q11.G R70.2 U23.G
NetC42_2: C42.2 R102.1 U11.7(XTLI) X1.3
NetC43_2: C43.2 R102.2 U11.6(XTLO) X1.1
NetC45_2: C45.2 J12.1(CT)
NetC49_2: C49.2 C50.2 L2.2 U11.16(AVDD33)
NetC56_2: C56.2 C57.2 C58.2 C59.2 L4.1 U11.8(AVDDL1) U11.13(AVDDL3) U11.19(AVDDL4) U11.44(AVDDL2)
NetJ12_D1: J12.D1 R84.1
NetJ12_D3: J12.D3 R83.1
NetL3_1: L3.1 U11.3(LX)
NetQ11_D: Q11.D R160.1
NetR75_1: R75.1 U11.40(WOL_INT)
NetR81_2: R81.2 U11.41(SD)
NetR82_2: R82.2 U11.9(RBIAS)
NetR244_2: R244.2 U29.6(OE)

Not connected (* = marked no-connect by the designer): U11 22(PPS)* 25(CLK_25M)* 26(LED_LINK10_100)* 42(SON)* 43(SOP)* 45(SIN)* 46(SIP)*

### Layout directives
differential pair; net class DIFF100: ETH1_TXRXA_N, ETH1_TXRXA_P, ETH1_TXRXB_N, ETH1_TXRXB_P, ETH1_TXRXC_N, ETH1_TXRXC_P, ETH1_TXRXD_N, ETH1_TXRXD_P

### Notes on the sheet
- Gigabit Ethernet
- Enabled by default
- PHYADDRESS0
- PHYADDRESS1
- PHYADDRESS2
- MODE[0]
- MODE[1]
- MODE[2]
- MODE[3]
- INT SELECT
- Parameter
- PHYADRESS[2:0]
- Default value
- 001
- Description
- PHY address set to 0x01
- Mode[3:0]
- Int select
- 0000
- 0
- BaseT, RGMII
- -

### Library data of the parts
C41 = 1000067: CAP CER 1000PF 50V 10% X7R 0402; Part_Type: Capacitor; Manufacturer: Murata; Manufacturer_Part_Number: GRM155R71H102KA01D; Digi_PN: 14050737; Component_Life_Cycle_State: Proven; Area: 0,95; Project: Adjustable Foundation
C42 C43 = 1001166: CAP CER 22PF 50V 5% NP0 0402; Part_Type: Capacitor; Manufacturer: Murata; Manufacturer_Part_Number: GRM1555C1H220JA01D; Note: 14050749 = Digi No. for GE WDNU; Digi_PN: 14050367; Component_Life_Cycle_State: Reviewed; Area: 0,95; Project: CCWMX6_SBC board; Temp_Coef: C0G, NP0
C44 C62 = 1000006: as C22-C26 on sheet 06 - JTAG, SWD, MicroSD, Mini PCIe, MicroSIM
C45 C48 C49 C51 C56 C57 = 1000006: as C139 on sheet 06 - JTAG, SWD, MicroSD, Mini PCIe, MicroSIM
C47 C54 = 1001168: CAP CER 10UF 10V 20% X5R 0402; Part_Type: Capacitor; Manufacturer: Samsung; Manufacturer_Part_Number: CL05A106MP5NUNC; Digi_PN: 14050689; Component_Life_Cycle_State: Reviewed; Area: 0,95; Project: CCWMX6_SBC board
C50 C52 C53 = 1001167: CAP CER 1UF 10V 10% X5R 0402; Part_Type: Capacitor; Manufacturer: Murata; Manufacturer_Part_Number: GRM155R61A105KE15D; Digi_PN: 14050399; Component_Life_Cycle_State: Reviewed; Area: 0.95; Project: CCWMX6_SBC board
C55 = 1000006: as C13 on sheet 06 - JTAG, SWD, MicroSD, Mini PCIe, MicroSIM
C58 C59 = 1001883: CAP CER 0.22UF 6.3V X7R 0402; Part_Type: Capacitor; Manufacturer: Taiyo Yuden; Manufacturer_Part_Number: JMK105B7224KV-F; Digi_PN: 14000067; Component_Life_Cycle_State: Reviewed; Area: 2.2; Project: Powerley Energy Bridge; Tolerance: 10%
J12 = 1002612: CONN MAGJACK 1PORT 1000 BASE-T IND; Part_Type: Connector; Manufacturer: XMultiple; Manufacturer_Part_Number: XMG-J1B2211NPA-1-DIG; Digi_PN: 18000772; Component_Life_Cycle_State: Created; Area: 339.5; Project: DIGI CC8X SOM
L2 L4 = 1001175: FERRITE BEAD 120 OHM .35A 0402; Part_Type: Filter; Manufacturer: Wurth Electronics Inc; Manufacturer_Part_Number: 7427927112; Digi_PN: 21000128; Component_Life_Cycle_State: Reviewed; Area: 1,12; Project: CCWMX6_SBC board
L3 = 1002610: FIXED IND 4.7UH 1.1A 110 MOHM; Manufacturer: Samsung; Manufacturer_Part_Number: CIG22L4R7MNE; Digi_PN: 21000590; Component_Life_Cycle_State: Created; Area: 5; Project: DIGI CC8X SOM; Tolerance: 20%
Q2 = 1000715: MOSFET N-CH 60V 115MA SOT-523F; Part_Type: Transistor; Manufacturer: Fairchild Semiconductor; Digi_PN: 17050797; Component_Life_Cycle_State: CAD Reviewed; Area: 3.06; Project: SmartMeter2; Note: 17050841 = Digi No. for GE WDNU
Q11 = 1000306: MOSFET N-CH 30V 500MA SOT-23; Part_Type: Transistor; Manufacturer: On Semiconductor; Digi_PN: 17050809; Component_Life_Cycle_State: Proven; Area: 10,92; Project: Adjustable Foundation
R16 R74 R75 R86-R101 = 1000537: RES 10.0K OHM 1/10W 1% 0402 SMD; Part_Type: Resistor; Manufacturer: Panasonic - ECG; Manufacturer_Part_Number: ERJ-2RKF1002X; Digi_PN: 13051084; Component_Life_Cycle_State: CAD Reviewed; Area: 0,95; Project: KITT; Power_WV_SRF: 100
R69 = 1000480: as R46 on sheet 06 - JTAG, SWD, MicroSD, Mini PCIe, MicroSIM
R70 R244 = 1000537: as R51 on sheet 06 - JTAG, SWD, MicroSD, Mini PCIe, MicroSIM
R71 = 1000208: RES 0.0 OHM 1/10W 0603; Part_Type: Resistor; Manufacturer: Panasonic - ECG; Manufacturer_Part_Number: ERJ-3GEY0R00V; Note: 13051103 = Digi No. for GE WDNU; Digi_PN: 13050568; Component_Life_Cycle_State: Reviewed; Area: 2.5; Project: Adjustable Foundation; Voltage: 75V
R72 R73 = 1000079: as R59 on sheet 07 - Console, UART, CAN
R81 = 1000038: RES 4.7K OHM 1/10W 5% 0402 SMD; Part_Type: Resistor; Manufacturer: Panasonic - ECG; Manufacturer_Part_Number: ERJ-2GEJ472X; Digi_PN: 13050549; Component_Life_Cycle_State: Proven; Area: 0,95; Project: Adjustable Foundation; Power_WV_SRF: 100; Tolerance: 5
R82 = 1000469: RES 2.37K OHM 1/10W 1% 0402 SMD; Part_Type: Resistor; Manufacturer: Panasonic - ECG; Manufacturer_Part_Number: ERJ-2RKF2371X; Component_Life_Cycle_State: Reviewed; Area: 0.95; Project: SDR Prototype RF Board; Power_WV_SRF: 100; Digi_PN: 13000089
R83 R84 = 1000465: RES 150 OHM 1/10W 1% 0402 SMD; Part_Type: Resistor; Manufacturer: Panasonic - ECG; Manufacturer_Part_Number: ERJ-2RKF1500X; Digi_PN: 13050557; Component_Life_Cycle_State: CAD Reviewed; Area: 0,95; Project: KITT; Power_WV_SRF: 100
R85 = 1000229: RES 0.0 OHM 1/2W 1210 SMD; Part_Type: Resistor; Manufacturer: Vishay Dale; Manufacturer_Part_Number: CRCW12100000Z0EA; Digi_PN: 13050962; Component_Life_Cycle_State: Proven; Area: 11,07; Project: Adjustable Foundation
R102 = 1001200: RES 12.0K OHM 1/10W 1% 0603 SMD; Part_Type: Resistor; Manufacturer: Yageo; Manufacturer_Part_Number: RC0603FR-0712KL; Digi_PN: 13050531; Component_Life_Cycle_State: Reviewed; Area: 2,5; Project: LuCoV2; Power_WV_SRF: 100; Tolerance: 1
R160 = 1000467: RES 100 OHM 1/10W 1% 0402 SMD; Part_Type: Resistor; Manufacturer: Panasonic - ECG; Manufacturer_Part_Number: ERJ-2RKF1000X; Digi_PN: 13051087; Component_Life_Cycle_State: CAD Reviewed; Area: 0,95; Project: KITT
U9 = 1001009: MOSFET DL N-CH 60V 410MA SOT-563; Part_Type: Transistor; Manufacturer: Diodes, Inc.; Digi_PN: 17050796; Component_Life_Cycle_State: Reviewed; Area: 2,89; Project: ConnectCore i.MX6 module
U11 = 1002583: IC TRANSCEIVER ETHERNET 48-QFN; Manufacturer: Qualcomm Atheros, Inc.; Digi_PN: 16000123; Component_Life_Cycle_State: Reviewed; Area: 52.56; Project: DIGI CC8X SOM
U23 = 1001163: MOSFET P-CH 20V 3.7A SOT23-3; Part_Type: IC; Manufacturer: Vishay Siliconix; Digi_PN: 17050358; Component_Life_Cycle_State: Reviewed; Area: 10.92; Project: CCWMX6_SBC board
U29 = 1002597: IC TRANSLATING TXRX 8XSON; Manufacturer: NXP Semiconductors; Manufacturer_Part_Number: NTS0102GT,115; Digi_PN: 16000138; Component_Life_Cycle_State: Created; Area: 3,9; Project: DIGI CC8X SOM
X1 = 1001497: SMCRY,25MHZ 50PPM 20PF RH100 EXT; Part_Type: Crystals-Oscillators; Manufacturer: Raltron; Digi_PN: 20000285; Component_Life_Cycle_State: Reviewed; Area: 3,2; Project: CCWMX6_SBC board

## Sheet 09 - Ethernet2.SchDoc: Ethernet2
size A3; PageSetup: Record=PageOptions¦CenterHorizontal=True¦CenterVertical=True¦PrintScale=0.70¦XCorrection=1.00¦YCorrection=1.00¦PrintKind=0¦BorderSize=5000000¦LeftOffset=0¦BottomOffset=0¦Orientation=2¦PaperLength=4200¦PaperWidth=2970¦Scale=100¦PaperSource=7¦PrintQuality=600¦MediaType=1¦DitherType=10¦PaperKind=A4¦PrintScaleMode=1; Author: Juan Anzola; SheetNumber: 9; SheetTotal: 17
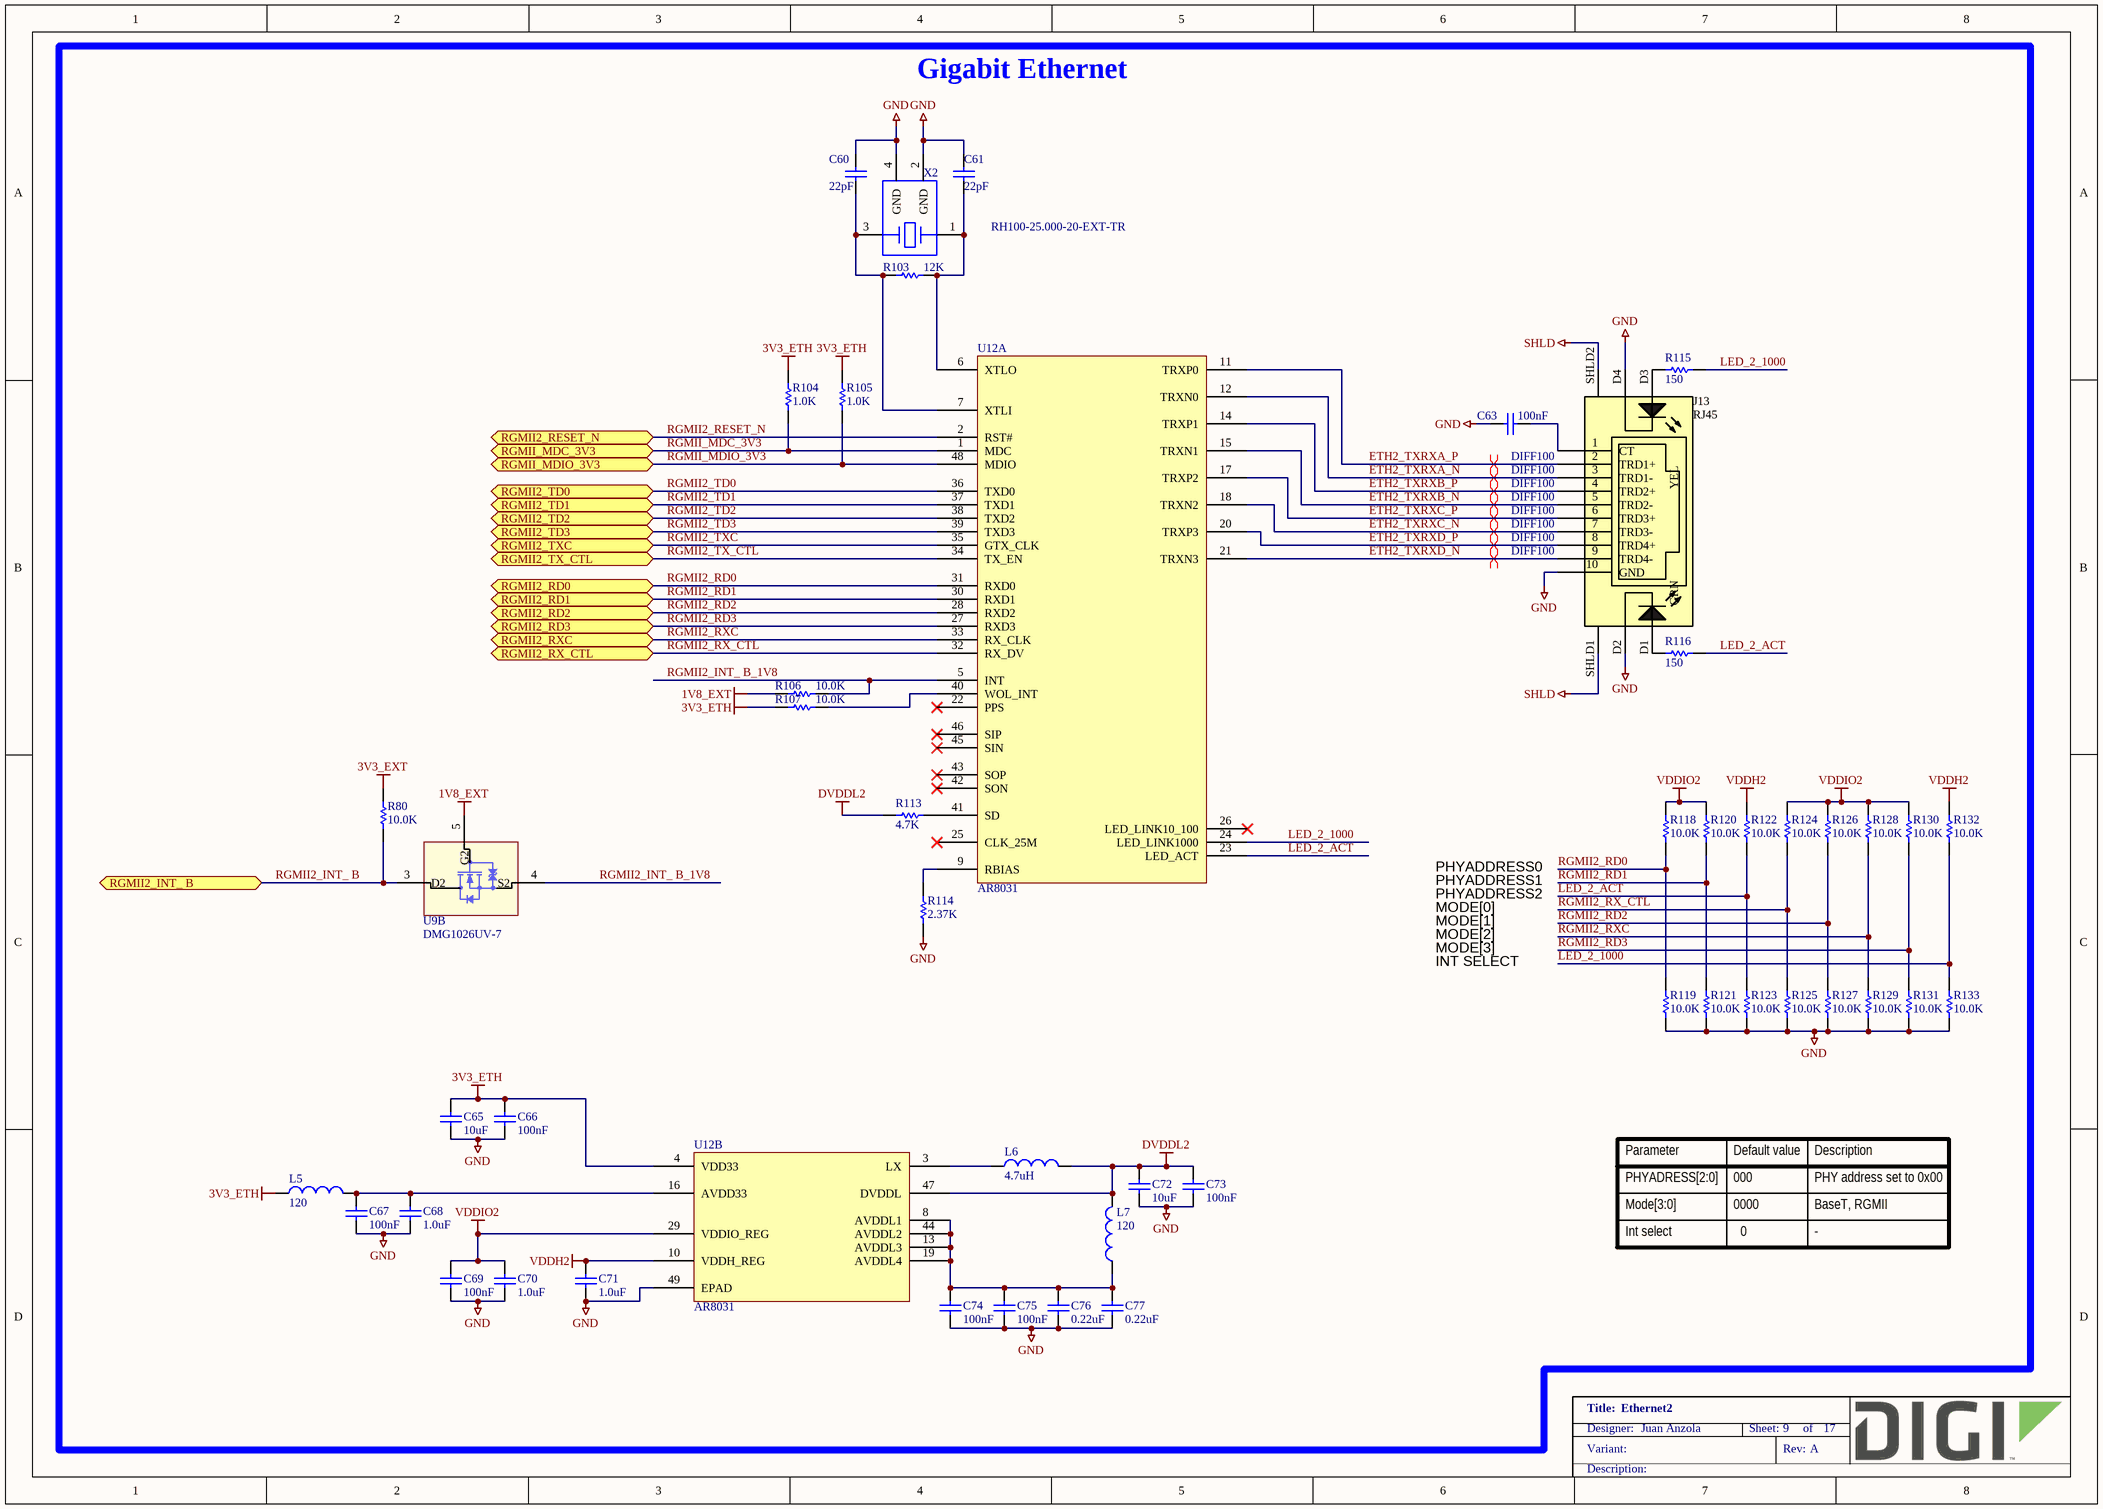
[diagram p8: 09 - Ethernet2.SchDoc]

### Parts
C60  22pF  [CAPC1005X55N]
C61  22pF  [CAPC1005X55N]
C63  100nF  [CAPC1005X55N]
C65  10uF  [CAPC1005X55N]
C66  100nF  [CAPC1005X55N]
C67  100nF  [CAPC1005X55N]
C68  1.0uF  [CAPC1005X55N]
C69  100nF  [CAPC1005X55N]
C70  1.0uF  [CAPC1005X55N]
C71  1.0uF  [CAPC1005X55N]
C72  10uF  [CAPC1005X55N]
C73  100nF  [CAPC1005X55N]
C74  100nF  [CAPC1005X55N]
C75  100nF  [CAPC1005X55N]
C76  0.22uF  [CAPC1005X55N]
C77  0.22uF  [CAPC1005X55N]
J13  RJ45  [XMULTIPLE_XMG-J1B211]
L5  120  [INDC1005X60N]
L6  4.7uH  [INDC2520X100L60N]
L7  120  [INDC1005X60N]
R80  10.0K  [RESC1005X40N]
R103  12K  [RESC1609X55N]
R104  1.0K  [RESC1005X40N]
R105  1.0K  [RESC1005X40N]
R106  10.0K  [RESC1005X40N]
R107  10.0K  [RESC1005X40N]
R113  4.7K  [RESC1005X40N]
R114  2.37K  [RESC1005X40N]
R115  150  [RESC1005X40N]
R116  150  [RESC1005X40N]
R118  10.0K  [RESC1005X40N]
R119  10.0K  [RESC1005X40N]
R120  10.0K  [RESC1005X40N]
R121  10.0K  [RESC1005X40N]
R122  10.0K  [RESC1005X40N]
R123  10.0K  [RESC1005X40N]
R124  10.0K  [RESC1005X40N]
R125  10.0K  [RESC1005X40N]
R126  10.0K  [RESC1005X40N]
R127  10.0K  [RESC1005X40N]
R128  10.0K  [RESC1005X40N]
R129  10.0K  [RESC1005X40N]
R130  10.0K  [RESC1005X40N]
R131  10.0K  [RESC1005X40N]
R132  10.0K  [RESC1005X40N]
R133  10.0K  [RESC1005X40N]
U9  DMG1026UV-7  [SOTFL50P160X60-6N]  (part B of 2)
U12  AR8031  [QFN40P600X600X80-49T380N]  (parts A,B of 2)
X2  RH100-25.000-20-EXT-TR  [OSC210P320X250X90-4N]

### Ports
RGMII2_INT_ B (bidir), RGMII2_RD0 (bidir), RGMII2_RD1 (bidir), RGMII2_RD2 (bidir), RGMII2_RD3 (bidir), RGMII2_RESET_N (bidir), RGMII2_RX_CTL (bidir), RGMII2_RXC (bidir), RGMII2_TD0 (bidir), RGMII2_TD1 (bidir), RGMII2_TD2 (bidir), RGMII2_TD3 (bidir), RGMII2_TX_CTL (bidir), RGMII2_TXC (bidir), RGMII_MDC_3V3 (bidir), RGMII_MDIO_3V3 (bidir)

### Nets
1V8_EXT: R106.2 U9.5(G2)
3V3_ETH: C65.2 C66.2 L5.1 R104.2 R105.2 R107.2 U12.4(VDD33)
3V3_EXT: R80.1
DVDDL2: C72.2 C73.2 L6.2 L7.2 R113.1 U12.47(DVDDL)
GND: C60.1 C61.1 C63.1 C65.1 C66.1 C67.1 C68.1 C69.1 C70.1 C71.1 C72.1 C73.1 C74.1 C75.1 C76.1 C77.1 J13.10(GND) J13.D2 J13.D4 R114.1 R119.1 R121.1 R123.1 R125.1 R127.1 R129.1 R131.1 R133.1 U12.49(EPAD) X2.2(GND) X2.4(GND)
SHLD: J13.SHLD1(SHLD) J13.SHLD2(SHLD)
VDDH2: C71.2 R122.2 R132.2 U12.10(VDDH_REG)
VDDIO2: C69.2 C70.2 R118.2 R120.2 R124.2 R126.2 R128.2 R130.2 U12.29(VDDIO_REG)
ETH2_TXRXA_N: J13.3(TRD1-) U12.12(TRXN0)
ETH2_TXRXA_P: J13.2(TRD1+) U12.11(TRXP0)
ETH2_TXRXB_N: J13.5(TRD2-) U12.15(TRXN1)
ETH2_TXRXB_P: J13.4(TRD2+) U12.14(TRXP1)
ETH2_TXRXC_N: J13.7(TRD3-) U12.18(TRXN2)
ETH2_TXRXC_P: J13.6(TRD3+) U12.17(TRXP2)
ETH2_TXRXD_N: J13.9(TRD4-) U12.21(TRXN3)
ETH2_TXRXD_P: J13.8(TRD4+) U12.20(TRXP3)
LED_2_1000: R115.2 R132.1 R133.2 U12.24(LED_LINK1000)
LED_2_ACT: R116.2 R122.1 R123.2 U12.23(LED_ACT)
RGMII2_INT_ B: R80.2 U9.3(D2) ; port RGMII2_INT_ B
RGMII2_INT_ B_1V8: R106.1 U9.4(S2) U12.5(INT)
RGMII2_RD0: R118.1 R119.2 U12.31(RXD0) ; port RGMII2_RD0
RGMII2_RD1: R120.1 R121.2 U12.30(RXD1) ; port RGMII2_RD1
RGMII2_RD2: R126.1 R127.2 U12.28(RXD2) ; port RGMII2_RD2
RGMII2_RD3: R130.1 R131.2 U12.27(RXD3) ; port RGMII2_RD3
RGMII2_RESET_N: U12.2(RST#) ; port RGMII2_RESET_N
RGMII2_RX_CTL: R124.1 R125.2 U12.32(RX_DV) ; port RGMII2_RX_CTL
RGMII2_RXC: R128.1 R129.2 U12.33(RX_CLK) ; port RGMII2_RXC
RGMII2_TD0: U12.36(TXD0) ; port RGMII2_TD0
RGMII2_TD1: U12.37(TXD1) ; port RGMII2_TD1
RGMII2_TD2: U12.38(TXD2) ; port RGMII2_TD2
RGMII2_TD3: U12.39(TXD3) ; port RGMII2_TD3
RGMII2_TX_CTL: U12.34(TX_EN) ; port RGMII2_TX_CTL
RGMII2_TXC: U12.35(GTX_CLK) ; port RGMII2_TXC
RGMII_MDC_3V3: R104.1 U12.1(MDC) ; port RGMII_MDC_3V3
RGMII_MDIO_3V3: R105.1 U12.48(MDIO) ; port RGMII_MDIO_3V3
NetC60_2: C60.2 R103.1 U12.7(XTLI) X2.3
NetC61_2: C61.2 R103.2 U12.6(XTLO) X2.1
NetC63_2: C63.2 J13.1(CT)
NetC67_2: C67.2 C68.2 L5.2 U12.16(AVDD33)
NetC74_2: C74.2 C75.2 C76.2 C77.2 L7.1 U12.8(AVDDL1) U12.13(AVDDL3) U12.19(AVDDL4) U12.44(AVDDL2)
NetJ13_D1: J13.D1 R116.1
NetJ13_D3: J13.D3 R115.1
NetL6_1: L6.1 U12.3(LX)
NetR107_1: R107.1 U12.40(WOL_INT)
NetR113_2: R113.2 U12.41(SD)
NetR114_2: R114.2 U12.9(RBIAS)

Not connected (* = marked no-connect by the designer): U12 22(PPS)* 25(CLK_25M)* 26(LED_LINK10_100)* 42(SON)* 43(SOP)* 45(SIN)* 46(SIP)*

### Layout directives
differential pair; net class DIFF100: ETH2_TXRXA_N, ETH2_TXRXA_P, ETH2_TXRXB_N, ETH2_TXRXB_P, ETH2_TXRXC_N, ETH2_TXRXC_P, ETH2_TXRXD_N, ETH2_TXRXD_P

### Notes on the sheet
- Gigabit Ethernet
- PHYADDRESS0
- PHYADDRESS1
- PHYADDRESS2
- MODE[0]
- MODE[1]
- MODE[2]
- MODE[3]
- INT SELECT
- Parameter
- PHYADRESS[2:0]
- Default value
- 000
- Description
- PHY address set to 0x00
- Mode[3:0]
- Int select
- 0000
- 0
- BaseT, RGMII
- -

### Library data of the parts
C60 C61 = 1001166: as C42 on sheet 08 - Ethernet1
C63 C66 C67 C69 C73-C75 = 1000006: as C139 on sheet 06 - JTAG, SWD, MicroSD, Mini PCIe, MicroSIM
C65 C72 = 1001168: as C47 on sheet 08 - Ethernet1
C68 C70 C71 = 1001167: as C50 on sheet 08 - Ethernet1
C76 C77 = 1001883: as C58 on sheet 08 - Ethernet1
J13 = 1002612: as J12 on sheet 08 - Ethernet1
L5 L7 = 1001175: as L2 on sheet 08 - Ethernet1
L6 = 1002610: as L3 on sheet 08 - Ethernet1
R80 R106 R107 R118-R133 = 1000537: as R16 on sheet 08 - Ethernet1
R103 = 1001200: as R102 on sheet 08 - Ethernet1
R104 R105 = 1000079: as R59 on sheet 07 - Console, UART, CAN
R113 = 1000038: as R81 on sheet 08 - Ethernet1
R114 = 1000469: as R82 on sheet 08 - Ethernet1
R115 R116 = 1000465: as R83 on sheet 08 - Ethernet1
U9 = 1001009: as U9 on sheet 08 - Ethernet1
U12 = 1002583: as U11 on sheet 08 - Ethernet1
X2 = 1001497: as X1 on sheet 08 - Ethernet1

## Sheet 10 - Displays and cameras.SchDoc: Displays and cameras
size A3; PageSetup: Record=PageOptions¦CenterHorizontal=True¦CenterVertical=True¦PrintScale=0.70¦XCorrection=1.00¦YCorrection=1.00¦PrintKind=0¦BorderSize=5000000¦LeftOffset=0¦BottomOffset=0¦Orientation=2¦PaperLength=4200¦PaperWidth=2970¦Scale=100¦PaperSource=7¦PrintQuality=600¦MediaType=1¦DitherType=10¦PaperKind=A4¦PrintScaleMode=1; Author: Juan Anzola; SheetNumber: 10; SheetTotal: 17
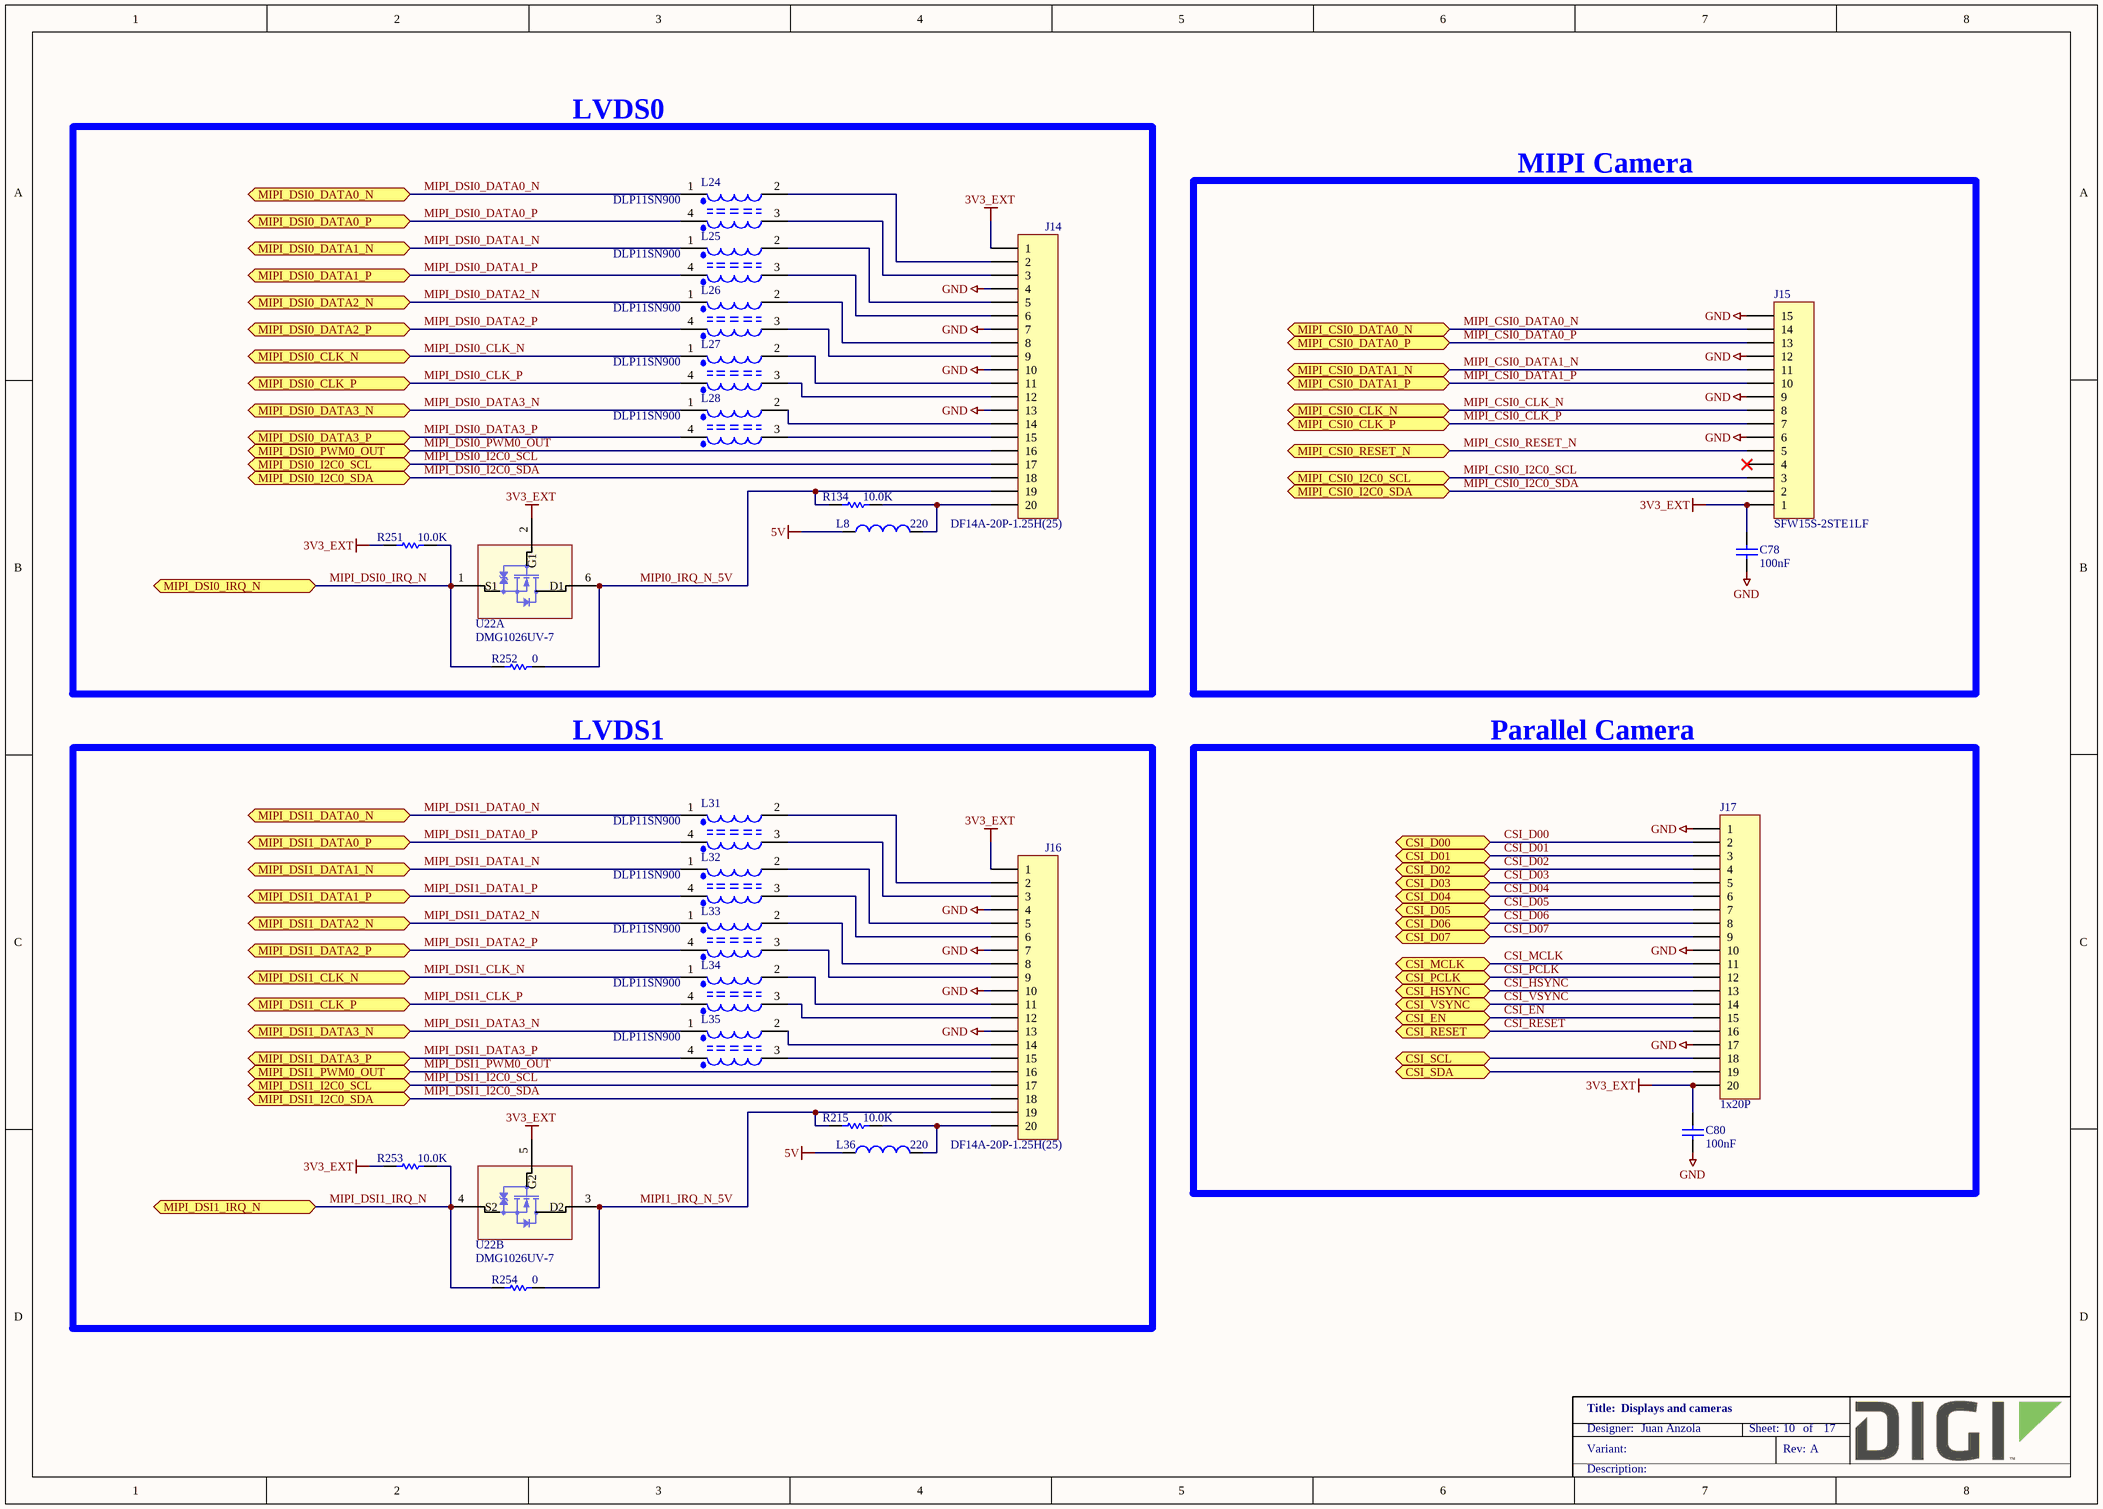
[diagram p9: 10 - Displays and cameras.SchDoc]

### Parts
C78  100nF  [CAPC1005X55N]
C80  100nF  [CAPC1005X55N]
J14  DF14A-20P-1.25H(25)  [HIROSE_DF14A-20P-1.25H]
J15  SFW15S-2STE1LF  [FCI_SFW15S-2STE1LF]
J16  DF14A-20P-1.25H(25)  [HIROSE_DF14A-20P-1.25H]
J17  1x20P  [omron_xf2m-2015-1a]
L8  220  [INDC2013X110N]
L24  DLP11SN900  [FIL_DLP11S]
L25  DLP11SN900  [FIL_DLP11S]
L26  DLP11SN900  [FIL_DLP11S]
L27  DLP11SN900  [FIL_DLP11S]
L28  DLP11SN900  [FIL_DLP11S]
L31  DLP11SN900  [FIL_DLP11S]
L32  DLP11SN900  [FIL_DLP11S]
L33  DLP11SN900  [FIL_DLP11S]
L34  DLP11SN900  [FIL_DLP11S]
L35  DLP11SN900  [FIL_DLP11S]
L36  220  [INDC2013X110N]
R134  10.0K  [RESC1005X40N]
R215  10.0K  [RESC1005X40N]
R251  10.0K  [RESC1005X40N]
R252  0  [RESC1005X40N]
R253  10.0K  [RESC1005X40N]
R254  0  [RESC1005X40N]
U22  DMG1026UV-7  [SOTFL50P160X60-6N]  (parts A,B of 2)

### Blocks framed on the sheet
LVDS0: J14 L8 L24-L28 R134 R251 R252 U22
MIPI Camera: C78 J15
LVDS1: J16 L31-L36 R215 R253 R254 U22
Parallel Camera: C80 J17

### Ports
CSI_D00 (bidir), CSI_D01 (bidir), CSI_D02 (bidir), CSI_D03 (bidir), CSI_D04 (bidir), CSI_D05 (bidir), CSI_D06 (bidir), CSI_D07 (bidir), CSI_EN (bidir), CSI_HSYNC (bidir), CSI_MCLK (bidir), CSI_PCLK (bidir), CSI_RESET (bidir), CSI_SCL (bidir), CSI_SDA (bidir), CSI_VSYNC (bidir), MIPI_CSI0_CLK_N (bidir), MIPI_CSI0_CLK_P (bidir), MIPI_CSI0_DATA0_N (bidir), MIPI_CSI0_DATA0_P (bidir), MIPI_CSI0_DATA1_N (bidir), MIPI_CSI0_DATA1_P (bidir), MIPI_CSI0_I2C0_SCL (bidir), MIPI_CSI0_I2C0_SDA (bidir), MIPI_CSI0_RESET_N (bidir), MIPI_DSI0_CLK_N (bidir), MIPI_DSI0_CLK_P (bidir), MIPI_DSI0_DATA0_N (bidir), MIPI_DSI0_DATA0_P (bidir), MIPI_DSI0_DATA1_N (bidir), MIPI_DSI0_DATA1_P (bidir), MIPI_DSI0_DATA2_N (bidir), MIPI_DSI0_DATA2_P (bidir), MIPI_DSI0_DATA3_N (bidir), MIPI_DSI0_DATA3_P (bidir), MIPI_DSI0_I2C0_SCL (bidir), MIPI_DSI0_I2C0_SDA (bidir), MIPI_DSI0_IRQ_N (bidir), MIPI_DSI0_PWM0_OUT (bidir), MIPI_DSI1_CLK_N (bidir), MIPI_DSI1_CLK_P (bidir), MIPI_DSI1_DATA0_N (bidir), MIPI_DSI1_DATA0_P (bidir), MIPI_DSI1_DATA1_N (bidir), MIPI_DSI1_DATA1_P (bidir), MIPI_DSI1_DATA2_N (bidir), MIPI_DSI1_DATA2_P (bidir), MIPI_DSI1_DATA3_N (bidir), MIPI_DSI1_DATA3_P (bidir), MIPI_DSI1_I2C0_SCL (bidir), MIPI_DSI1_I2C0_SDA (bidir), MIPI_DSI1_IRQ_N (bidir), MIPI_DSI1_PWM0_OUT (bidir)

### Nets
3V3_EXT: C78.2 C80.2 J14.1 J15.1 J16.1 J17.20 R251.1 R253.1 U22.2(G1) U22.5(G2)
5V: L8.1 L36.1
GND: C78.1 C80.1 J14.4 J14.7 J14.10 J14.13 J15.6 J15.9 J15.12 J15.15 J16.4 J16.7 J16.10 J16.13 J17.1 J17.10 J17.17
CSI_D00: J17.2 ; port CSI_D00
CSI_D01: J17.3 ; port CSI_D01
CSI_D02: J17.4 ; port CSI_D02
CSI_D03: J17.5 ; port CSI_D03
CSI_D04: J17.6 ; port CSI_D04
CSI_D05: J17.7 ; port CSI_D05
CSI_D06: J17.8 ; port CSI_D06
CSI_D07: J17.9 ; port CSI_D07
CSI_EN: J17.15 ; port CSI_EN
CSI_HSYNC: J17.13 ; port CSI_HSYNC
CSI_MCLK: J17.11 ; port CSI_MCLK
CSI_PCLK: J17.12 ; port CSI_PCLK
CSI_RESET: J17.16 ; port CSI_RESET
CSI_SCL: J17.18 ; port CSI_SCL
CSI_SDA: J17.19 ; port CSI_SDA
CSI_VSYNC: J17.14 ; port CSI_VSYNC
MIPI0_IRQ_N_5V: J14.19 R134.1 R252.2 U22.6(D1)
MIPI1_IRQ_N_5V: J16.19 R215.1 R254.2 U22.3(D2)
MIPI_CSI0_CLK_N: J15.8 ; port MIPI_CSI0_CLK_N
MIPI_CSI0_CLK_P: J15.7 ; port MIPI_CSI0_CLK_P
MIPI_CSI0_DATA0_N: J15.14 ; port MIPI_CSI0_DATA0_N
MIPI_CSI0_DATA0_P: J15.13 ; port MIPI_CSI0_DATA0_P
MIPI_CSI0_DATA1_N: J15.11 ; port MIPI_CSI0_DATA1_N
MIPI_CSI0_DATA1_P: J15.10 ; port MIPI_CSI0_DATA1_P
MIPI_CSI0_I2C0_SCL: J15.3 ; port MIPI_CSI0_I2C0_SCL
MIPI_CSI0_I2C0_SDA: J15.2 ; port MIPI_CSI0_I2C0_SDA
MIPI_CSI0_RESET_N: J15.5 ; port MIPI_CSI0_RESET_N
MIPI_DSI0_CLK_N: L27.1 ; port MIPI_DSI0_CLK_N
MIPI_DSI0_CLK_P: L27.4 ; port MIPI_DSI0_CLK_P
MIPI_DSI0_DATA0_N: L24.1 ; port MIPI_DSI0_DATA0_N
MIPI_DSI0_DATA0_P: L24.4 ; port MIPI_DSI0_DATA0_P
MIPI_DSI0_DATA1_N: L25.1 ; port MIPI_DSI0_DATA1_N
MIPI_DSI0_DATA1_P: L25.4 ; port MIPI_DSI0_DATA1_P
MIPI_DSI0_DATA2_N: L26.1 ; port MIPI_DSI0_DATA2_N
MIPI_DSI0_DATA2_P: L26.4 ; port MIPI_DSI0_DATA2_P
MIPI_DSI0_DATA3_N: L28.1 ; port MIPI_DSI0_DATA3_N
MIPI_DSI0_DATA3_P: L28.4 ; port MIPI_DSI0_DATA3_P
MIPI_DSI0_I2C0_SCL: J14.17 ; port MIPI_DSI0_I2C0_SCL
MIPI_DSI0_I2C0_SDA: J14.18 ; port MIPI_DSI0_I2C0_SDA
MIPI_DSI0_IRQ_N: R251.2 R252.1 U22.1(S1) ; port MIPI_DSI0_IRQ_N
MIPI_DSI0_PWM0_OUT: J14.16 ; port MIPI_DSI0_PWM0_OUT
MIPI_DSI1_CLK_N: L34.1 ; port MIPI_DSI1_CLK_N
MIPI_DSI1_CLK_P: L34.4 ; port MIPI_DSI1_CLK_P
MIPI_DSI1_DATA0_N: L31.1 ; port MIPI_DSI1_DATA0_N
MIPI_DSI1_DATA0_P: L31.4 ; port MIPI_DSI1_DATA0_P
MIPI_DSI1_DATA1_N: L32.1 ; port MIPI_DSI1_DATA1_N
MIPI_DSI1_DATA1_P: L32.4 ; port MIPI_DSI1_DATA1_P
MIPI_DSI1_DATA2_N: L33.1 ; port MIPI_DSI1_DATA2_N
MIPI_DSI1_DATA2_P: L33.4 ; port MIPI_DSI1_DATA2_P
MIPI_DSI1_DATA3_N: L35.1 ; port MIPI_DSI1_DATA3_N
MIPI_DSI1_DATA3_P: L35.4 ; port MIPI_DSI1_DATA3_P
MIPI_DSI1_I2C0_SCL: J16.17 ; port MIPI_DSI1_I2C0_SCL
MIPI_DSI1_I2C0_SDA: J16.18 ; port MIPI_DSI1_I2C0_SDA
MIPI_DSI1_IRQ_N: R253.2 R254.1 U22.4(S2) ; port MIPI_DSI1_IRQ_N
MIPI_DSI1_PWM0_OUT: J16.16 ; port MIPI_DSI1_PWM0_OUT
NetJ14_2: J14.2 L24.2
NetJ14_3: J14.3 L24.3
NetJ14_5: J14.5 L25.2
NetJ14_6: J14.6 L25.3
NetJ14_8: J14.8 L26.2
NetJ14_9: J14.9 L26.3
NetJ14_11: J14.11 L27.2
NetJ14_12: J14.12 L27.3
NetJ14_14: J14.14 L28.2
NetJ14_15: J14.15 L28.3
NetJ14_20: J14.20 L8.2 R134.2
NetJ16_2: J16.2 L31.2
NetJ16_3: J16.3 L31.3
NetJ16_5: J16.5 L32.2
NetJ16_6: J16.6 L32.3
NetJ16_8: J16.8 L33.2
NetJ16_9: J16.9 L33.3
NetJ16_11: J16.11 L34.2
NetJ16_12: J16.12 L34.3
NetJ16_14: J16.14 L35.2
NetJ16_15: J16.15 L35.3
NetJ16_20: J16.20 L36.2 R215.2

Not connected (* = marked no-connect by the designer): J15 4*

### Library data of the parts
C78 C80 = 1000006: as C139 on sheet 06 - JTAG, SWD, MicroSD, Mini PCIe, MicroSIM
J14 J16 = 1001132: CONN HEADER 20POS 1.25MM R/A SMD; Part_Type: Connector; Manufacturer: Hirose; Digi_PN: 18050231; Component_Life_Cycle_State: Reviewed; Area: 206.34; Project: CCWMX6_SBC board
J15 = 1001866: CONN FFC FPC VERT 15POS 1MM SMD; Part_Type: Connector; Manufacturer: FCI; Digi_PN: 18000730; Component_Life_Cycle_State: Reviewed; Area: 128,76; Project: CCiMX6 SBC MFG TEST BOARD
J17 = 1001145: CONN FPC 20POS 0.5MM PITCH SMD; Part_Type: Connector; Manufacturer: Omron; Manufacturer_Part_Number: XF2M-2015-1A; Digi_PN: 18000675; Component_Life_Cycle_State: Reviewed; Area: 69,09; Project: CCWMX6_SBC board
L8 L36 = 1001174: FERRITE BEAD 220 OHM 2.0A 0805; Manufacturer: Wurth Electronics Inc; Manufacturer_Part_Number: 742792022; Digi_PN: 21000146; Component_Life_Cycle_State: Reviewed; Area: 4.24; Project: CCWMX6_SBC board
L24-L28 L31-L35 = 1001014: CHOKE COIL COMMON MODE 150MA SMD; Part_Type: Inductor; Manufacturer: Murata; Manufacturer_Part_Number: DLP11SN900HL2L; Component_Life_Cycle_State: Reviewed; Area: 3.94; Project: ResMed RF Test Interface Board; Digi_PN: 21000531
R134 R215 R251 R253 = 1000537: as R51 on sheet 06 - JTAG, SWD, MicroSD, Mini PCIe, MicroSIM
R252 R254 = 1000076: RES 0.0 OHM 1/10W 0402 SMD; Part_Type: Resistor; Manufacturer: Panasonic - ECG; Manufacturer_Part_Number: ERJ-2GE0R00X; Digi_PN: 13050387; Component_Life_Cycle_State: Proven; Area: 0,95; Power_WV_SRF: 10
U22 = 1001009: MOSFET DL N-CH 60V 410MA SOT-563; Part_Type: Transistor; Manufacturer: Diodes, Inc.; Digi_PN: 17050796; Component_Life_Cycle_State: Reviewed; Area: 2,89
